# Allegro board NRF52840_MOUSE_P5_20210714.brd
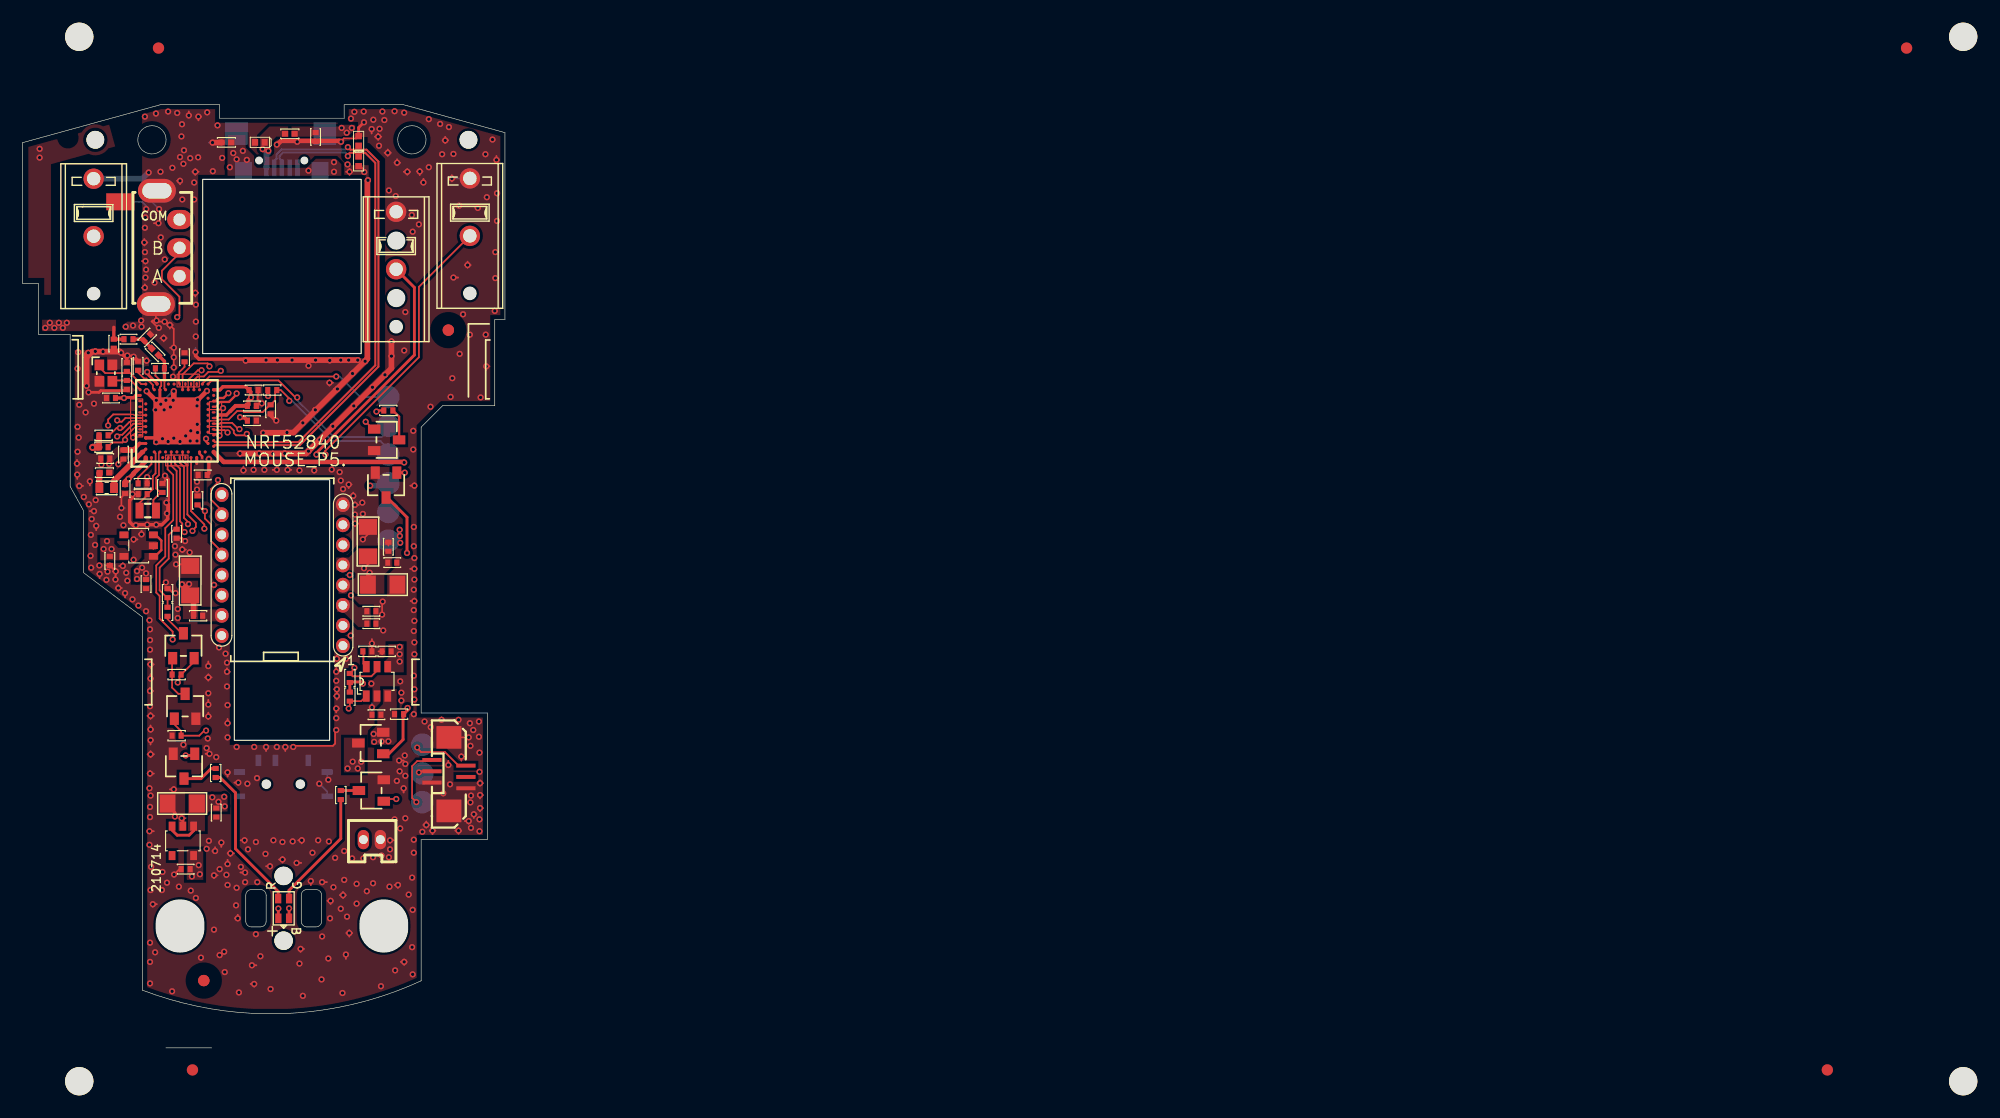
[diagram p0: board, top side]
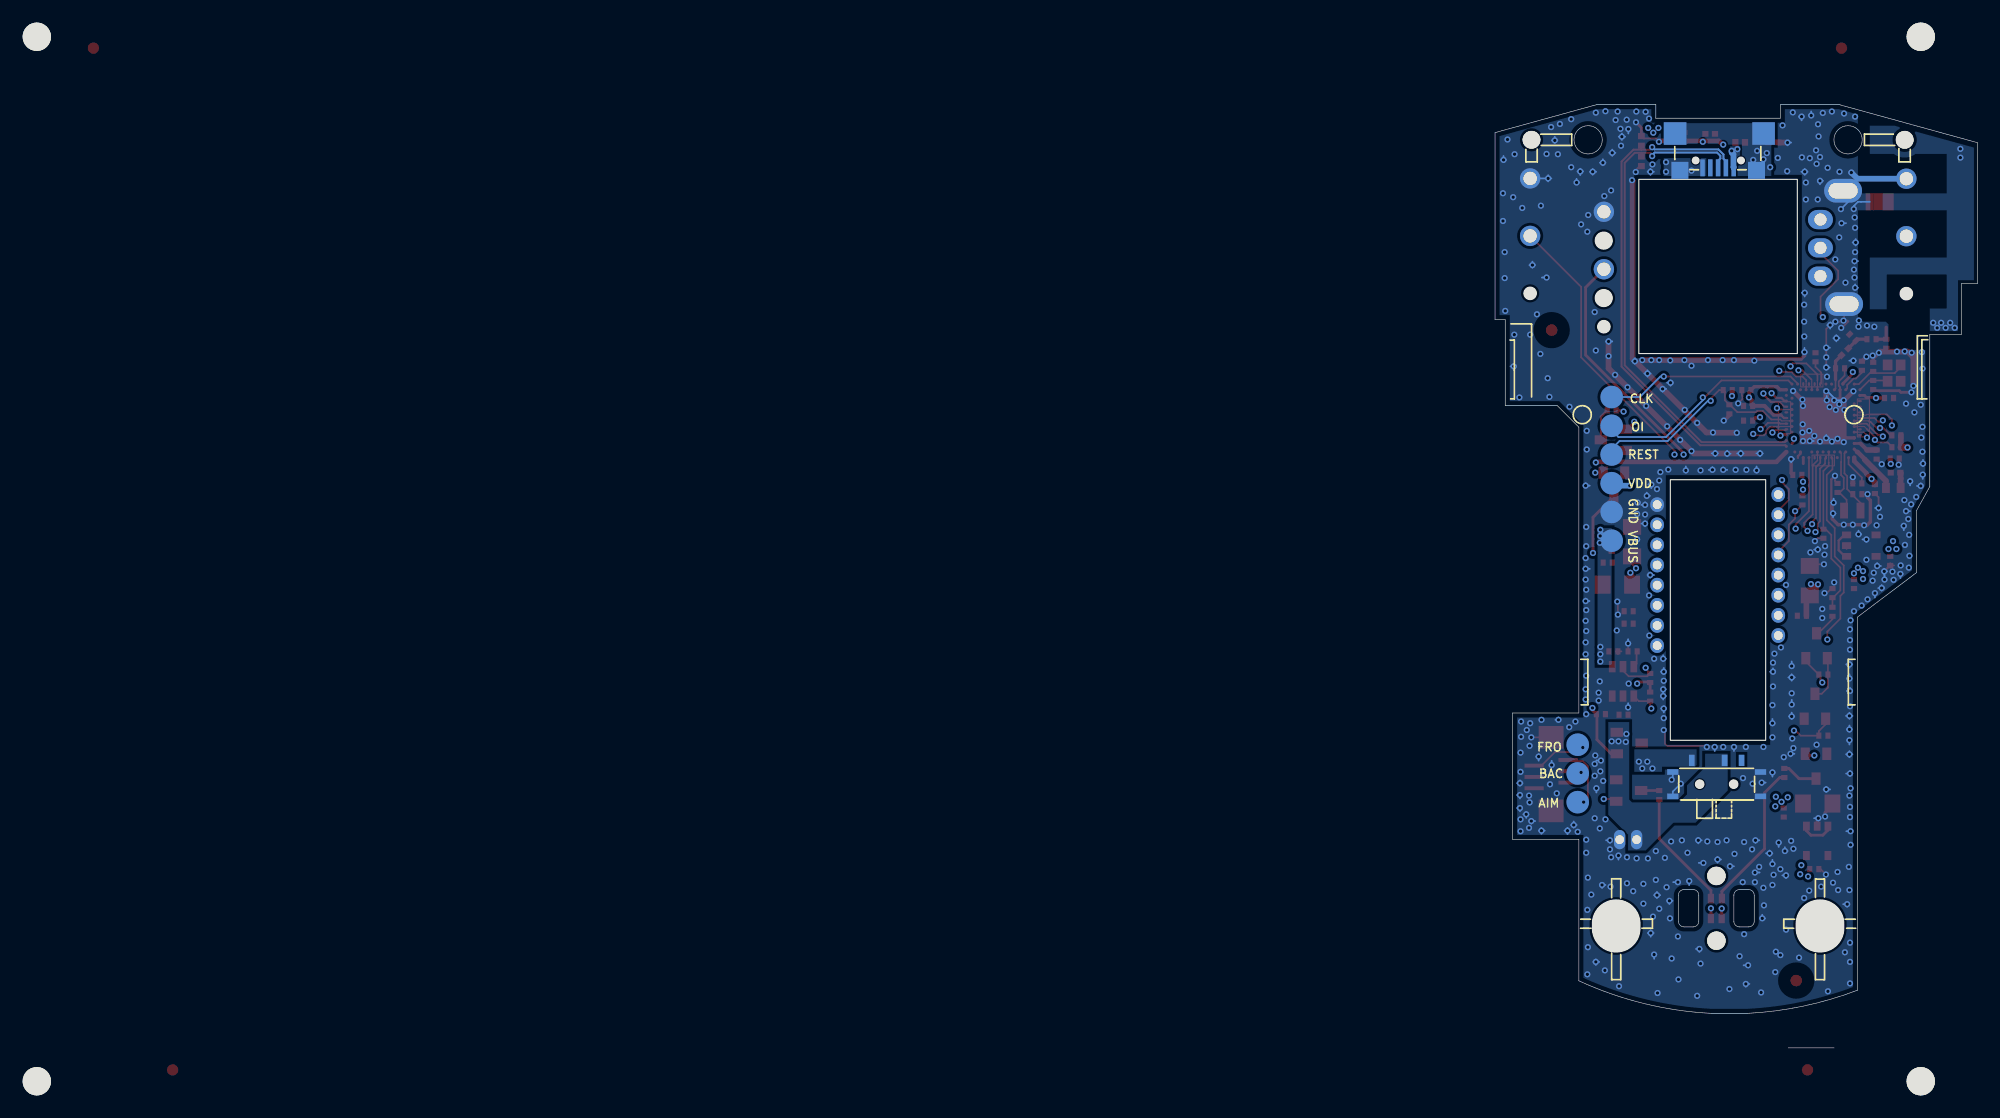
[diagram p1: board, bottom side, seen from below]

Outline 42.6 x 83.38 mm; copper layers: TOP, LAYER2, LAYER3, BOTTOM. Coordinates in mm from the lower left corner of the outline.
Outline path: circle c11.42,80.27 r1.25 ; rectangle 15.9,61.38 29.9,76.78 ; rectangle 18.7,27.19 27.12,50.23 ; circle c34.38,80.27 r1.25 ; 12.65,0 16.7,0 ; 0,80.03 0,67.56 1.41,67.56 1.41,63.06 4.2,63.06 4.2,49.62 5.38,47.48 5.38,42.01 10.6,38.07 10.6,5.09 arc(15.38,3.69) 20.32,3.05 23.48,3.05 arc(29.48,3.93) 35.2,5.93 35.2,18.42 41.05,18.42 41.05,29.6 35.2,29.6 35.2,54.87 37.1,56.77 41.7,56.77 41.7,64.37 42.6,64.37 42.6,80.91 33.61,83.38 28.4,83.38 28.4,82.18 17.4,82.18 17.4,83.38 12.19,83.38 0,80.03 ; 19.71,13.49 arc(19.85,13.85) 20.21,13.99 21.01,13.99 arc(21.36,13.85) 21.51,13.49 21.51,11.19 arc(21.36,10.84) 21.01,10.69 20.21,10.69 arc(19.85,10.84) 19.71,11.19 19.71,13.49 ; 24.61,13.49 arc(24.75,13.85) 25.11,13.99 25.91,13.99 arc(26.26,13.85) 26.41,13.49 26.41,11.19 arc(26.26,10.84) 25.91,10.69 25.11,10.69 arc(24.75,10.84) 24.61,11.19 24.61,13.49

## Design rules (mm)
net group RF2-MOUSE: nets N00074 N454705
net group USB: nets D_N D_P
net group 0_0762: nets BAT_ADC BLE_MODE BTN_RIGHT LED_B LED_G LED_R LLPM_MODE MOTION RESET SCLK WHELL_A WHELL_B WHELL_COM
net group W0_1R: nets N00048

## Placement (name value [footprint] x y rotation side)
C1  12pF  [C0402]  9.2 60.2 90 top
C2  12pF  [C0402]  9.2 58.6 270 top
C5  100nF  [C0402]  10.6 49.9 0 top
C6  4.7uF  [C0402]  15.9 50.65 0 top
C7  100nF  [C0402]  20.25 56.75 0 top
C8  100nF  [C0402]  20.4 58.15 0 top
C9  820pF  [C0402]  14.3 61.05 90 top
C11  100pF  [C0402]  10.2 60.3 90 top
C12  100nF  [C0402]  7.8 57.45 180 top
C14  1uF  [C0402]  9.05 49.4 270 top
C15  1uF  [C0402]  8.9 52.45 90 top
C16  47nF  [C0402]  7.3 52.1 180 top
C17  9pF  [C0402]  10.6 48.95 180 top
C18  9pF  [C0402]  12.35 49.5 90 top
C20  4.7uF  [C0402]  20.25 55.45 0 top
C22  100nF  [C0402]  25.87 80.52 90 top
C25  NC/0.8pF  [C0402]  12.12 60.08 180 top
C26  NC/0.5pF  [C0402]  11 62.8 45 top
C27  100nF  [C0402]  21.9 56.45 90 top
C28  10uF  [C0402]  30.8 37.5 0 top
C29  100nF  [C0402]  30.8 38.6 0 top
C30  4.7uF  [C0402]  31.25 29.45 180 top
C32  1uF  [C0402]  7.7 43.05 270 top
C33  1uF  [C0402]  14.4 15.8 180 top
C34  NC  [C0402]  13.6 45.45 270 top
C35  1uF  [C0402]  10.9 41 270 top
C36  1uF  [C0402]  17.1 20.8 270 top
C58  0R  [C0402]  9.35 62.65 180 top
C59  NC  [C0402]  8.05 62.25 270 top
C60  10uF  [C1206]  30.5 44.75 90 top
C61  10uF  [C1206]  31.8 40.95 0 top
C62  33uF  [C1206]  14.8 41.3 90 top
C63  100nF  [C0402]  32.3 44.3 90 top
C64  100nF  [C0402]  32.65 42.9 0 top
C65  10uF  [C1206]  14.1 21.6 180 top
D1  AZ5325-01F.R7G  [DFN1006P2E]  20.95 80.05 180 top
D2  AZ5325-01F.R7G  [DFN1006P2E]  29.67 78.38 270 top
D3  AZ5325-01F.R7G  [DFN1006P2E]  29.68 80.17 90 top
FB1  120R  [L0402]  23.6 80.8 0 top
FB2  120R  [L0402]  18 80.05 180 top
J1  Micro_USB  [PCBCOMPONENT_1_-_DUPLICATE]  24.28 77.28 180 bottom
J3  Scroll whell  [ENCODE-DIP-5PIN_-_DUPLICATE]  12.36 70.72 90 top
J4  SW_KEY  [KEYE]  6.27 71.75 0 top
J5  FPC_CON  [FPC_6PINLGUH]  39.15 22.95 270 top
J6  SW_KEY  [KEYE]  39.5 71.78 0 top
J7  SW_KEY  [KEYD1]  32.99 68.83 0 top
J8  POWER_SWITCH  [KEY-20210303]  23.03 23.31 180 bottom
J9  BAT_CON  [CON5-0303]  30.85 18.41 0 top
L2  10uH  [L0603]  7.42 49.5 0 top
L3  15nH  [L0402]  7.23 50.85 180 top
L4  0R  [L0402]  11.7 61.52 135 top
LED1  LED_RGB  [LED-SMD-1615-RGB_2]  23.05 12.32 180 top
MARK  -  [unnamed#3]  176.4 1.05 0 top
MARK#2  -  [unnamed#4]  0 85.38 0 top
MARK#3  -  [unnamed#5]  0 1.05 0 top
MARK#4  -  [unnamed#6]  176.4 85.38 0 top
NOREF  -  [unnamed]  23.05 15.2 0 top
NOREF#2  -  [unnamed#2]  37.6 63.45 0 top
NOREF#3  -  [unnamed#2]  16 5.95 0 top
NOREF#4  -  [unnamed]  39.38 80.27 0 top
NOREF#5  -  [unnamed]  23.05 9.48 0 top
NOREF#6  -  [unnamed]  13.9 10.78 0 top
NOREF#7  -  [unnamed]  31.9 10.78 0 top
NOREF#8  -  [unnamed]  6.42 80.27 0 top
Q2604  SI2301  [SOT_23]  14.2 35.55 0 top
Q2605  SI2301  [SOT_23]  30.75 26.95 90 top
R2  10K  [R0402]  22.05 58.15 180 top
R21  1M  [R0402]  7.15 53.1 180 top
R22  1M  [R0402]  7.15 54.15 180 top
R23  12R  [R0402]  15.5 38.2 180 top
R24  2K  [R0402]  17.05 24.3 270 top
R25  2K  [R0402]  28.1 22.35 270 top
R26  2K  [R0402]  32.3 56.35 180 top
R27  2K  [R0402]  30.45 35.05 180 top
R30  10K  [R0402]  15.45 48.4 90 top
R31  1M5  [R0402]  12.8 38.55 270 top
R32  180K  [R0402]  12.8 40.2 270 top
R33  1M  [R0402]  13.6 33 0 top
R34  1M  [R0402]  13.6 27.6 0 top
R42  1M  [R0402]  32.15 35.05 0 top
R43  1M  [R0402]  33.25 29.5 180 top
R44  10K  [R0402]  28.9 32.7 270 top
R45  10K  [R0402]  28.9 31.05 90 top
SHORT  short  [SHORT-1P5X1P8-2PIN]  9.16 74.79 0 top
TP2  TP_0.7  [TP_20]  32.3 54.99 180 bottom
TP3  TP_0.7  [TP_20]  32.3 57.53 180 bottom
TP4  TP_0.7  [TP_20]  32.3 47.38 180 bottom
TP5  TP_0.7  [TP_20]  32.3 52.45 180 bottom
TP6  TP_0.7  [TP_20]  32.3 44.83 180 bottom
TP7  TP_0.7  [TP_20]  32.3 49.91 180 bottom
TP8  TP_0.7  [TP_20]  35.3 26.8 180 bottom
TP9  TP_0.7  [TP_20]  35.3 24.26 180 bottom
TP10  TP_0.7  [TP_20]  35.3 21.72 180 bottom
U1  nRF52840-QIAA  [AQFN50P700X700X85_HS-74N]  13.62 55.43 90 top
U2  PAW3370DM  [PMW3360DM]  28.28 35.56 180 top
U1401  LDO 1.8V  [SOT-23-5L]  10.25 44.4 90 top
U1403  2N7002K-7  [SOT_23]  14.25 24.9 180 top
U1404  2N7002K-7  [SOT_23]  30.8 22.75 90 top
U1405  2N7002K-7  [SOT_23]  32.15 53.75 270 top
U1406  HX4057A  [SOT23-6]  31.3 32.4 90 top
U1407  LDO 3.3V  [SOT-23-5L]  14.15 18.3 180 top
U1408  2N7002K-7  [SOT_23]  14.35 30.2 0 top
U1409  2N7002K-7  [SOT_23]  32.1 49.75 180 top
X1  32MHz  [BT-XTAL_2016]  7.35 59.65 270 top
X2  32.768kHz  [XTAL_2012]  11.05 47.5 0 top

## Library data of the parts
C1 C2 C5-C9 C11 C12 C14-C18 C20 C22 C25 C27 = CAP
C26 C28-C30 C32-C36 C58-C65 = ceramic_Cap
D1-D3 = ESD_BI_DFN1006P2E
FB1 FB2 = IND_F
J1 = UN1159C-N1211-7H_1
J3 = Header-2_0
J4 J6 J7 = Header-2_3
J5 = Header-2_7
J8 = Header-2_5
J9 = Header-2_6
L2 L3 = IND
L4 = Inductors
LED1 = LED_RGB_1
Q2604 Q2605 = P-MOSFET_SOT_23
R2 = RES_1
R21-R27 R30-R34 R42-R45 = ceramic_Res
SHORT = TP_0
TP2-TP10 = TP
U1 = nRF52840_QIAA
U2 = DCDC_SY8254RAC_0
U1401 U1407 = DC_DC_SOT_23_2
U1403-U1405 U1408 U1409 = N-MOSFET_SOT_23
U1406 = DC_DC_SOT_23_4
X1 = CRYSTAL_3225
X2 = XTAL_2-pin

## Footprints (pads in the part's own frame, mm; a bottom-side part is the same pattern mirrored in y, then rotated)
AQFN50P700X700X85_HS-74N
  rect 4.15x4.15 smd: 74(0,0)
  oval 0.2x0.343 smd: A8(-1.25,3.25) A10(-0.75,3.25) A12(-0.25,3.25) A14(0.25,3.25) A16(0.75,3.25) A18(1.25,3.25) A20(1.75,3.25) AD10(-0.75,-3.25) AD12(-0.25,-3.25) AD14(0.25,-3.25) AD16(0.75,-3.25) AD18(1.25,-3.25)
  round 0.275 smd: A22(2.25,3.25) A23(2.75,3.25) AA24(3.25,-2.25) AB2(-2.75,-2.5) AC5(-2,-2.75) AC9(-1,-2.75) AC11(-0.5,-2.75) AC13(0,-2.75) AC15(0.5,-2.75) AC17(1,-2.75) AC19(1.5,-2.75) AC21(2,-2.75) AC24(3.25,-2.75) AD2(-2.75,-3.25) AD4(-2.25,-3.25) AD6(-1.75,-3.25) AD8(-1.25,-3.25) AD20(1.75,-3.25) AD22(2.25,-3.25) AD23(2.75,-3.25) B1(-3.25,2.75) B3(-2.5,2.75) B5(-2,2.75) B7(-1.5,2.75) B9(-1,2.75) B11(-0.5,2.75) B13(0,2.75) B15(0.5,2.75) B17(1,2.75) B19(1.5,2.75) B24(3.25,2.75) C1(-3.25,2.25) D2(-2.75,2) D23(2.75,2) E24(3.25,1.75) F2(-2.75,1.5) F23(2.75,1.5) G1(-3.25,1.25) H2(-2.75,1) H23(2.75,1) J24(3.25,0.75) K2(-2.75,0.5) L24(3.25,0.25) M2(-2.75,0) P2(-2.75,-0.5) P23(2.75,-0.5) T2(-2.75,-1) T23(2.75,-1) U1(-3.25,-1.25) V23(2.75,-1.5) W1(-3.25,-1.75) Y2(-2.75,-2) Y23(2.75,-2)
  oval 0.343x0.2 smd: J1(-3.25,0.75) L1(-3.25,0.25) N1(-3.25,-0.25) N24(3.25,-0.25) R1(-3.25,-0.75) R24(3.25,-0.75) U24(3.25,-1.25) W24(3.25,-1.75)
BT-XTAL_2016
  rect 0.95x0.85 smd: 1(-0.725,-0.575) 2(0.725,-0.575) 3(0.725,0.575) 4(-0.725,0.575)
C0402
  rect 0.45x0.55 smd: 1(-0.4,0) 2(0.4,0)
C1206
  rect 1.4x1.6 smd: 1(-1.3,0) 2(1.3,0)
CON5-0303
  oval 1x1.7 hole 0.7: 1(-0.75,0) 2(0.75,0)
DFN1006P2E
  rect 0.55x0.6 smd: 1(-0.425,0) 2(0.425,0)
ENCODE-DIP-5PIN_-_DUPLICATE
  oval 1.7x2.2 hole 1: 1(-2.5,-1.5) 2(0,-1.5) 3(2.5,-1.5)
  oval 2.1x3.35 hole 1.3x2.5: 4(-4.97,0.59) 5(5.05,0.5)
FPC_6PINLGUH
  rect 0.35x1.7 smd: 1(0,0) 2(-0.5,-3) 3(-1,0) 4(-1.5,-3) 5(-2,0) 6(-2.5,-3)
  rect 2x2.2 smd: 7(-4.5,-1.5) 8(2,-1.5)
KEY-20210303
  round 0.75 hole 0.75 unplated: (-1.5,0) (1.5,0)
  rect 0.5x1 smd: 1(-2.2,2.1) 2(0.7,2.1) 3(2.2,2.1)
  rect 1x0.5 smd: 4(3.875,1.075) 5(3.875,-1.075) 6(-3.875,-1.075) 7(-3.875,1.075)
KEYD1
  round 1.1 hole 1.1 unplated: (0,-5.08)
  round 1.5 hole 1.5 unplated: (0.011,2.532) (0.011,-2.548)
  round 1.8 hole 1.1: 1(0,0) 2(0,5.08)
KEYE
  round 1.1 hole 1.1 unplated: (0,-5.08)
  round 1.8 hole 1.1: 1(0,0) 2(0,5.08)
L0402
  rect 0.55x0.508 smd: 1(-0.424,0) 2(0.424,0)
L0603
  rect 0.7x0.9 smd: 1(-0.648,0) 2(0.648,0)
LED-SMD-1615-RGB_2
  rect 0.55x0.85 smd: 1(0.483,-0.876) 2(-0.483,-0.874) 3(-0.483,0.876) 4(0.467,0.876)
PCBCOMPONENT_1_-_DUPLICATE
  round 0.6 hole 0.6 unplated: (-0.605,1.17) (3.395,1.17)
  rect 0.4x1.5 smd: 1(2.75,0.521) 2(2.062,0.521) 3(1.375,0.521) 4(0.688,0.521) 5(0,0.521)
  rect 1.5x1.5 smd: 6(4.77,0.3) 9(-2,0.3)
  rect 2x2 smd: 7(5.391,3.55) 8(-2.421,3.55)
PMW3360DM
  oval 1.2x1.3 hole 0.7: 1(0,0) 2(0,-1.78) 3(0,-3.56) 4(0,-5.34) 5(0,-7.12) 6(0,-8.9) 7(0,-10.68) 8(0,-12.46) 9(10.7,-13.35) 10(10.7,-11.57) 11(10.7,-9.79) 12(10.7,-8.01) 13(10.7,-6.23) 14(10.7,-4.45) 15(10.7,-2.67) 16(10.7,-0.89)
R0402
  rect 0.45x0.55 smd: 1(-0.4,0) 2(0.4,0)
SHORT-1P5X1P8-2PIN
  rect 0.7x1.5 smd: 1(0.35,0)
  rect 1.8x1.5 smd: 2(-0.875,0)
SOT23-6
  rect 1x0.6 smd: 1(-1.3,0.95) 2(-1.3,0) 3(-1.3,-0.95) 4(1.3,-0.95) 5(1.3,0) 6(1.3,0.95)
SOT-23-5L
  rect 0.6x0.8 smd: 1(-0.95,-1.3) 2(0,-1.3) 3(0.95,-1.3) 4(0.95,1.3) 5(-0.95,1.3)
SOT_23
  rect 0.8x1.1 smd: 1(-0.95,-1.1) 2(0.95,-1.1) 3(0,1.1)
TP_20
  round 2 smd: 1(0,0)
unnamed
  round 1.6 hole 1.6 unplated: (0,0)
unnamed#2
  round 1 smd: (0,0) (0,0)
unnamed#3
  round 1 smd: (-17,-3)
  round 2.5 hole 2.5 unplated: (-5,-4)
unnamed#4
  round 2.5 hole 2.5 unplated: (5,4)
  round 1 smd: (12,3)
unnamed#5
  round 2.5 hole 2.5 unplated: (5,-4)
  round 1 smd: (15,-3)
unnamed#6
  round 1 smd: (-10,3)
  round 2.5 hole 2.5 unplated: (-5,4)
XTAL_2012
  rect 0.7x1.4 smd: 1(-0.725,0) 2(0.725,0)

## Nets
GND: C1.2 C2.2 C5.2 C6.2 C7.2 C8.2 C9.2 C11.2 C12.2 C14.2 C15.1 C16.2 C17.2 C18.2 C20.2 C22.1 C25.2 C26.2 C27.1 C28.2 C29.2 C30.2 C32.2 C33.2 C34.2 C35.2 C36.2 C59.2 C60.2 C61.2 C62.2 C63.2 C64.2 C65.2 D1.2 D2.2 D3.2 FB2.2 J3.4 J3.5 J4.2 J5.1 J5.2 J5.7 J5.8 J6.2 J7.2 J8.4 J8.5 J8.6 J8.7 J9.2 R27.1 R32.1 R34.1 R42.1 SHORT.1 TP4.1 U1.74 U1.B7(VSS) U1.F23(VSS_PA) U2.8(GND) U1401.2(GND) U1403.2(SOURCE) U1404.2(SOURCE) U1405.2(SOURCE) U1406.2(GND) U1407.2(GND) U1408.2(SOURCE) U1409.2(SOURCE) X1.2(GND1) X1.4(GND2)
VBAT_IN: C30.1 J8.2 J9.1 Q2604.2(SOURCE) Q2605.2(SOURCE) R33.2 R43.2 U1406.3(BAT)
VBAT_OUT: C36.1 C65.1 J8.1 Q2605.3(DRAIN) U1407.1(VIN) U1407.3(EN)
VBUS: D1.1 FB1.1 J1.1(VBUS)
VBUS_NRF: C22.2 FB1.2 R42.2 TP6.1 U1.AD2(VBUS) U1406.4(VCC) U1409.1(GATE)
VDD: C6.1 C7.1 C8.1 C12.1 C14.1 C32.1 C60.1 C61.1 C62.1 C63.1 C64.1 R2.2 R21.2 R22.2 R23.2 R30.2 R44.2 R45.2 TP7.1 U1.A22(VDD#A22) U1.AD14(VDD#AD14) U1.AD23(VDD#AD23) U1.B1(VDD#B1) U1.W1(VDD#W1) U1.Y2(VDDH) U2.4(VDD) U2.5(VDDIO) U1401.5(VOUT)
VDD_LED: C33.1 C35.1 LED1.4(A) U1401.1(VIN) U1401.3(EN) U1407.5(VOUT)
BAT_ADC: C34.1 R31.1 R32.2 U1.K2(P0.05/AIN3)
BAT_MON_EN: R34.2 U1.L1(P0.06) U1408.1(GATE)
BLE_MODE: U1.B17(P1.12)
BTN_LEFT: J4.1 U1.A12(P0.02/AIN0)
BTN_PCB_AIM: J5.6 TP10.1 U1.J1(P0.04/AIN2)
BTN_PCB_BACK: J5.4 TP9.1 U1.AD18(P0.22)
BTN_PCB_FRONT: J5.5 TP8.1 U1.AD20(P0.24)
BTN_RIGHT: J6.1 U1.B15(P1.14)
BTN_WHEEL: J7.1 U1.A14(P1.15)
D_N: D3.1 J1.2(D-) U1.AD4(D-)
D_P: D2.1 J1.3(D+) U1.AD6(D+)
DCCH: U1.AB2(DCCH)
DEC1: C5.1 U1.C1(DEC1)
DEC2: U1.A18(DEC2)
DEC3: C11.1 U1.D23(DEC3)
DEC4_6: C15.2 C16.1 L3.1 U1.B5(DEC4) U1.E24(DEC6)
LED_B: U1.V23(P1.03) U1405.1(GATE)
LED_G: U1.T23(P1.05) U1404.1(GATE)
LED_R: U1.P23(P1.07) U1403.1(GATE)
LLPM_MODE: U1.B19(P1.11)
MISO: R30.1 U1.AD10(P0.15) U2.12(MISO)
MOSI: U1.AD12(P0.17) U2.11(MOSI)
MOTION: U1.AC17(P0.21) U2.9(MOTION)
NCHRG: R45.1 U1.N1(P0.08) U1406.1(CHRG)
NSTDBY: R44.1 U1.P2(P1.08) U1406.5(STDBY)
PMW_RESET: U1.U1(P0.12) U2.7(RESET)
PWM_CS: U1.AD8(P0.13) U2.13(/CS)
RESET: C27.2 R2.1 TP5.1 U1.AC13(P0.18/RESET)
SCLK: U1.AC11(P0.16) U2.10(SCLK)
SW1: U1.R24(P1.06)
SWDCLK: TP3.1 U1.AA24(SWDCLK)
SWDIO: TP2.1 U1.AC24(SWDIO)
WHELL_A: J3.2 R22.1 U1.B13(P0.03/AIN1)
WHELL_B: J3.1 R21.1 U1.B11(P0.28/AIN4)
WHELL_COM: J3.3 U1.B9(P0.30/AIN6)
XC1: C1.1 U1.B24(XC1) X1.1(XIN)
XC2: C2.1 U1.A23(XC2) X1.3(XOUT)
N00013: C9.1 U1.N24(DEC5)
N00015: C20.1 U1.AC5(DECUSB)
N00024: L2.1 L3.2
N00025: L2.2 U1.B3(DCC)
N00047: C17.1 U1.D2(P0.00/XL1) X2.1(INP)
N00048: C18.1 U1.F2(P0.01/XL2) X2.2(OUT)
N00074: C25.1 L4.1 U1.H23(ANT)
N00235: FB2.1 J1.5(GND) J1.6(SHIELD2) J1.7(SHIELD3) J1.8(SHIELD4) J1.9(SHIELD5)
N372358: R23.1 U2.15(LED_P)
N372603: C28.1 C29.1 U2.3(VDDPIX)
N379055: LED1.1(C_RED) R24.2
N379073: LED1.2(C_GREEN) R25.2
N379080: LED1.3(C_BLUE) R26.2
N379134: R24.1 U1403.3(DRAIN)
N379451: R25.1 U1404.3(DRAIN)
N379621: R26.1 U1405.3(DRAIN)
N384910: R27.2 U1406.6(PROG)
N404039: Q2604.1(GATE) R33.1 U1408.3(DRAIN)
N404214: Q2604.3(DRAIN) R31.2
N445725: Q2605.1(GATE) R43.1 U1409.3(DRAIN)
N454705: C26.1 C58.1 L4.2
N455919: C58.2 C59.1 SHORT.2

Pads without a net: J1 4; J5 3; J8 3; U1 A8 A10 A16 A20 AC9 AC15 AC19 AC21 AD16 AD22 G1 H2 J24 L24 M2 R1 T2 U24 W24 Y23; U2 1 2 6 14 16; U1401 4; U1407 4

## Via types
v1: diameter 0.55, hole 0.3, TOP to BOTTOM, 613 vias

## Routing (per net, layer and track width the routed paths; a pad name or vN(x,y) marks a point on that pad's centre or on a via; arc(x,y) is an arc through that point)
GND: length 672.7
  TOP w0.15: 16.5,25.77 v1(16.5,26) ; v1(16.5,26) 16.5,26.15 ; v1(16.5,26) 16.16,26 ; v1(16.5,26) 16.65,26 ; v1(17,17.4) 17.18,17.4 ; v1(17,17.4) 17,17.73 ; v1(17,17.4) 16.76,17.4 ; v1(17,17.4) 17,17.22 ; 27.1,58.54 v1(27.1,58.8) ; v1(27.1,58.8) 27.41,58.8 ; v1(27.1,58.8) 26.9,58.8 ; v1(27.1,58.8) 27.1,59 ; C63.2 32.45,44.7 ; C63.2 32.3,44.4 ; C63.2 32.03,44.7 ; C63.2 32.3,44.85 ; U1409.2 31.15,51.1 ; U1409.2 31.15,50.6 ; U1409.2 31.4,50.85 ; U1409.2 30.83,50.85 ; v1(34.6,39.5) 34.6,39.73 ; v1(34.6,39.5) 34.6,39.35 ; v1(34.6,39.5) 34.26,39.5 ; v1(34.6,39.5) 34.75,39.5 ; v1(39.4,20.05) 39.4,20.22 ; v1(39.4,20.05) 39.06,20.05 ; v1(39.4,20.05) 39.4,19.82 ; v1(39.4,20.05) 39.57,20.05 ; 16.4,33.6 v1(16.4,33.75) ; v1(16.4,33.75) 16.56,33.75 ; v1(16.4,33.75) 16.4,34.16 ; v1(16.4,33.75) 16.25,33.75 ; 27.52,31.1 v1(27.75,31.1) ; v1(27.75,31.1) 27.75,30.8 ; v1(27.75,31.1) 27.95,31.1 ; v1(27.75,31.1) 27.75,31.3 ; J3.5 11.86,76 ; J3.5 11.63,75.77 ; J3.5 12.13,75.77 ; J3.5 11.86,75.48 ; v1(27.75,31.7) 27.75,31.87 ; v1(27.75,31.7) 27.75,31.37 ; v1(27.75,31.7) 27.52,31.7 ; v1(27.75,31.7) 27.92,31.7 ; J5.7 37.65,27.63 ; J5.7 37.65,27.12 ; J5.7 37.41,27.45 ; J5.7 v1(39.4,27.45) ; v1(35.65,19.7) 35.65,20.01 ; v1(35.65,19.7) 35.65,19.47 ; v1(35.65,19.7) 35.88,19.7 ; v1(35.65,19.7) 35.39,19.7 ; R42.1 31.92,35.05 ; R42.1 31.43,35.05 ; R42.1 31.75,35.22 ; R42.1 31.75,34.8 ; v1(19.2,52.55) 19.2,52.69 ; v1(19.2,52.55) 19.2,52.3 ; v1(19.2,52.55) 18.95,52.55 ; 39.3,68.97 v1(39.3,69.2) ; v1(39.3,69.2) 39.56,69.2 ; v1(39.3,69.2) 39.07,69.2 ; v1(39.3,69.2) 39.3,69.5 ; 16.4,32.47 v1(16.4,32.75) ; v1(16.4,32.75) 16.12,32.75 ; v1(16.4,32.75) 16.69,32.75 ; v1(16.4,32.75) 16.4,33.03 ; 11.55,44.11 U1401.2 ; U1401.2 11.55,44.58 ; U1401.2 11.37,44.4 ; U1401.2 11.82,44.4 ; v1(25.75,51.05) 25.94,51.05 ; v1(25.75,51.05) 25.75,50.86 ; v1(25.75,51.05) 25.54,51.05 ; v1(25.75,51.05) 25.75,51.35 ; C16.2 6.9,51.6 v1(6.95,51.55) ; v1(39.85,20.65) 39.85,20.84 ; v1(39.85,20.65) 39.66,20.65 ; v1(39.85,20.65) 40.1,20.65 ; v1(39.85,20.65) 39.85,20.33 ; 24.37,8.75 v1(24.55,8.75) ; v1(24.55,8.75) 24.55,8.93 ; v1(24.55,8.75) 24.85,8.75 ; v1(24.55,8.75) 24.55,8.48 ; v1(29.35,46.35) 29.67,46.35 ; v1(29.35,46.35) 29.35,46.54 ; v1(29.35,46.35) 29.16,46.35 ; v1(29.35,46.35) 29.35,46.11 ; v1(34.6,49.7) 34.77,49.7 ; v1(34.6,49.7) 34.6,49.53 ; v1(34.6,49.7) 34.6,49.91 ; v1(34.6,49.7) 34.24,49.7 ; 11.1,31.55 v1(11.25,31.55) ; v1(11.25,31.55) 11.53,31.55 ; v1(11.25,31.55) 11.25,31.84 ; v1(11.25,31.55) 11.25,31.4 ; v1(14.05,20.3) 14.35,20.3 ; v1(14.05,20.3) 14.05,20.49 ; v1(14.05,20.3) 13.86,20.3 ; v1(14.05,20.3) 14.05,20.11 ; v1(35.07,77.47) 35.32,77.47 ; v1(35.07,77.47) 35.07,77.16 ; v1(35.07,77.47) 34.83,77.47 ; v1(35.07,77.47) 35.07,77.72 ; v1(27.7,33.25) 27.7,33.58 ; v1(27.7,33.25) 27.94,33.25 ; v1(27.7,33.25) 27.52,33.25 ; v1(27.7,33.25) 27.7,33.05 ; 6.61,41.9 v1(6.8,41.9) ; v1(6.8,41.9) 6.8,42.07 ; v1(6.8,41.9) 6.97,41.9 ; v1(6.8,41.9) 6.8,41.53 ; v1(32.45,18.35) 32.78,18.35 ; v1(32.45,18.35) 32.27,18.35 ; v1(32.45,18.35) 32.45,18.53 ; v1(32.45,18.35) 32.45,18.12 ; v1(31.4,80.55) 31.68,80.55 ; v1(31.4,80.55) 31.4,80.27 ; v1(31.4,80.55) 31.4,80.83 ; v1(31.4,80.55) 31.11,80.55 ; v1(22.95,16.65) 22.95,16.87 ; v1(22.95,16.65) 23.17,16.65 ; v1(22.95,16.65) 22.65,16.65 ; v1(22.95,16.65) 22.95,16.38 ; 27.52,34.4 v1(27.75,34.4) ; v1(27.75,34.4) 27.75,34.7 ; v1(27.75,34.4) 27.75,34.19 ; v1(27.75,34.4) 27.96,34.4 ; v1(40.4,22.35) 40.65,22.35 ; v1(40.4,22.35) 40.23,22.35 ; v1(40.4,22.35) 40.4,22.05 ; v1(40.4,22.35) 40.4,22.52 ; v1(28.3,13.5) 28.3,13.78 ; v1(28.3,13.5) 28.55,13.5 ; v1(28.3,13.5) 28.3,13.25 ; v1(28.3,13.5) 28.02,13.5 ; 37.45,25 v1(37.6,25) ; v1(37.6,25) 37.79,25 ; v1(37.6,25) 37.6,24.85 ; v1(37.6,25) 37.6,25.38 ; v1(14.67,82.42) 14.67,82.78 ; v1(14.67,82.42) 14.89,82.42 ; v1(14.67,82.42) 14.53,82.42 ; v1(14.67,82.42) 14.67,82.28 ; 28,48.02 U2.8 ; U2.8 28.28,47.74 ; U2.8 28.57,48.02 ; U2.8 28.28,48.3 ; C8.2 20.8,57.67 20.75,57.62 20.75,57.35 21.11,56.99 ; v1(18.1,28.7) 18.3,28.7 ; v1(18.1,28.7) 18.1,28.51 ; v1(18.1,28.7) 18.1,29.07 ; v1(18.1,28.7) 17.91,28.7 ; v1(16.45,52.05) 16.45,52.22 ; v1(16.45,52.05) 16.62,52.05 ; v1(16.45,52.05) 16.25,52.05 ; J6.2 39.5,77.06 ; J6.2 39.87,76.86 ; J6.2 39.5,76.69 ; J6.2 39.33,76.86 ; v1(11.5,12.7) 11.85,12.7 ; v1(11.5,12.7) 11.5,12.85 ; v1(11.5,12.7) 11.35,12.7 ; v1(11.5,12.7) 11.5,12.48 ; v1(18.35,17.2) 18.35,17.44 ; v1(18.35,17.2) 18.66,17.2 ; v1(18.35,17.2) 18.11,17.2 ; v1(18.35,17.2) 18.35,16.94 ; 35.4,76.35 v1(35.4,76.5) ; v1(35.4,76.5) 35.4,76.83 ; v1(35.4,76.5) 35.55,76.5 ; v1(35.4,76.5) 35.16,76.5 ; v1(12.46,62.74) 12.71,62.74 ; v1(12.46,62.74) 12.18,62.74 ; v1(12.46,62.74) 12.46,63 ; v1(12.46,62.74) 12.46,62.46 ; 20.9,52.69 v1(20.9,52.55) 20.9,52.29 ; 22.09,51.1 v1(22.45,51.1) ; v1(22.45,51.1) 22.59,51.1 ; v1(22.45,51.1) 22.45,51.31 ; v1(22.45,51.1) 22.45,50.96 ; v1(10.5,45.4) 10.67,45.4 ; v1(10.5,45.4) 10.26,45.4 ; v1(10.5,45.4) 10.5,45.23 ; v1(10.5,45.4) 10.5,45.72 ; X1.4 7.93,60.74 ; X1.4 7.93,60.19 ; X1.4 8.11,60.37 ; X1.4 7.73,60.37 ; 38.5,18.92 v1(38.5,19.2) ; v1(38.5,19.2) 38.72,19.2 ; v1(38.5,19.2) 38.5,19.42 ; v1(38.5,19.2) 38.21,19.2 ; C32.2 7.92,42.65 ; C32.2 7.36,42.65 ; C32.2 7.7,42.43 ; C32.2 7.7,42.85 ; 10.55,67.2 v1(10.8,67.2) ; v1(10.8,67.2) 10.8,67.49 ; v1(10.8,67.2) 10.98,67.2 ; v1(10.8,67.2) 10.8,67.02 ; 33.25,25.24 v1(33.25,25.4) ; v1(33.25,25.4) 33.65,25.4 ; v1(33.25,25.4) 33.25,25.55 ; v1(33.25,25.4) 33.1,25.4 ; v1(40.95,60.25) 41.23,60.25 ; v1(40.95,60.25) 40.8,60.25 ; v1(40.95,60.25) 40.95,59.96 ; v1(40.95,60.25) 40.95,60.4 ; v1(9.05,40.2) 9.24,40.2 ; v1(9.05,40.2) 9.05,39.82 ; v1(9.05,40.2) 9.05,40.38 ; v1(9.05,40.2) 8.87,40.2 ; 28.92,48.8 v1(29.2,48.8) ; v1(29.2,48.8) 29.2,48.65 ; v1(29.2,48.8) 29.2,49.09 ; v1(29.2,48.8) 29.35,48.8 ; 21.51,16.05 v1(21.85,16.05) ; v1(21.85,16.05) 21.85,15.85 ; v1(21.85,16.05) 22.05,16.05 ; v1(21.85,16.05) 21.85,16.27 ; v1(40.4,21.2) 40.65,21.2 ; v1(40.4,21.2) 40.4,21.39 ; v1(40.4,21.2) 40.4,20.92 ; v1(40.4,21.2) 40.21,21.2 ; 11.04,29.35 v1(11.3,29.35) ; v1(11.3,29.35) 11.3,29.09 ; v1(11.3,29.35) 11.3,29.62 ; v1(11.3,29.35) 11.59,29.35 ; v1(11,50.45) C5.2 ; C5.2 11,49.75 ; C5.2 11.17,49.9 ; C5.2 10.85,49.9 ; v1(5,49.67) 5.33,49.67 ; v1(5,49.67) 5,49.91 ; v1(5,49.67) 4.85,49.67 ; v1(5,49.67) 5,49.53 ; 26.31,14.65 v1(26.45,14.65) ; v1(26.45,14.65) 26.87,14.65 ; v1(26.45,14.65) 26.45,14.79 ; v1(26.45,14.65) 26.45,14.5 ; 33.7,7.33 v1(33.7,7.6) ; v1(33.7,7.6) 33.92,7.6 ; v1(33.7,7.6) 33.7,7.82 ; v1(33.7,7.6) 33.4,7.6 ; v1(16.4,30.35) 16.4,30.76 ; v1(16.4,30.35) 16.4,30.21 ; v1(16.4,30.35) 16.55,30.35 ; v1(16.4,30.35) 16.26,30.35 ; 10.75,60.75 v1(10.95,60.75) ; v1(10.95,60.75) 10.95,60.55 ; v1(10.95,60.75) 11.15,60.75 ; v1(10.95,60.75) 10.95,60.95 ; v1(23.4,51.1) 23.4,51.34 ; v1(23.4,51.1) 23.4,50.93 ; v1(23.4,51.1) 23.73,51.1 ; v1(23.4,51.1) 23.23,51.1 ; 33.97,77.19 v1(33.97,77.45) ; v1(33.97,77.45) 33.97,77.69 ; v1(33.97,77.45) 34.21,77.45 ; v1(33.97,77.45) 33.67,77.45 ; v1(32.57,62.45) 32.57,62.68 ; v1(32.57,62.45) 32.25,62.45 ; v1(32.57,62.45) 32.81,62.45 ; D2.2 29.82,77.95 30.17,77.6 v1(30.17,77.42) ; v1(25.45,14.75) 25.64,14.75 ; v1(25.45,14.75) 25.45,14.39 ; v1(25.45,14.75) 25.28,14.75 ; v1(25.45,14.75) 25.45,14.92 ; 15.05,66.75 v1(15.25,66.75) ; v1(15.25,66.75) 15.25,66.43 ; v1(15.25,66.75) 15.5,66.75 ; v1(15.25,66.75) 15.25,66.95 ; v1(11.3,32.65) 11.5,32.65 ; v1(11.3,32.65) 11.13,32.65 ; v1(11.3,32.65) 11.3,32.48 ; v1(11.3,32.65) 11.3,33.02 ; 41.65,78.5 v1(41.85,78.5) ; v1(41.85,78.5) 42.07,78.5 ; v1(41.85,78.5) 41.85,78.84 ; v1(41.85,78.5) 41.85,78.3 ; 16.4,29.08 v1(16.4,29.3) ; v1(16.4,29.3) 16.4,29.63 ; v1(16.4,29.3) 16.18,29.3 ; v1(16.4,29.3) 16.63,29.3 ; v1(8.22,42.12) 8.44,42.12 ; v1(8.22,42.12) 8.22,41.82 ; v1(8.22,42.12) 7.96,42.12 ; v1(8.22,42.12) 8.22,42.34 ; v1(4.8,51.65) 5.04,51.65 ; v1(4.8,51.65) 4.6,51.65 ; v1(4.8,51.65) 4.8,51.97 ; v1(4.8,51.65) 4.8,51.42 ; v1(13.55,42.75) 14.65,42.75 C62.2 ; 12,72.75 v1(12,72.9) ; v1(12,72.9) 11.61,72.9 ; v1(12,72.9) 12.15,72.9 ; v1(12,72.9) 12,73.07 ; 36.84,29 v1(37,29) ; v1(37,29) 37.26,29 ; v1(37,29) 37,29.2 ; v1(37,29) 37,28.84 ; v1(24.2,16.35) 24.6,16.35 ; v1(24.2,16.35) 24.2,16.19 ; v1(24.2,16.35) 24.05,16.35 ; v1(24.2,16.35) 24.2,16.5 ; C34.2 14.1,45.05 v1(14.35,44.8) ; v1(11.2,19.15) 11.57,19.15 ; v1(11.2,19.15) 11.2,19.34 ; v1(11.2,19.15) 11.2,19 ; v1(11.2,19.15) 11.05,19.15 ; 37.63,76.86 v1(37.91,76.86) ; v1(37.91,76.86) 37.91,77.14 ; v1(37.91,76.86) 38.17,76.86 ; v1(37.91,76.86) 37.91,76.6 ; v1(4.82,50.67) 4.82,50.83 ; v1(4.82,50.67) 4.63,50.67 ; v1(4.82,50.67) 4.82,50.3 ; v1(4.82,50.67) 4.98,50.67 ; v1(15.25,77.45) 15.25,77.7 ; v1(15.25,77.45) 15.25,77.18 ; v1(15.25,77.45) 15.54,77.45 ; v1(15.25,77.45) 15,77.45 ; 31.97,79.12 v1(32.25,79.12) ; v1(32.25,79.12) 32.52,79.12 ; v1(32.25,79.12) 32.25,78.86 ; v1(32.25,79.12) 32.25,79.41 ; 11.04,25.95 v1(11.3,25.95) ; v1(11.3,25.95) 11.3,25.69 ; v1(11.3,25.95) 11.59,25.95 ; v1(11.3,25.95) 11.3,26.23 ; 13.87,44.05 v1(14.1,44.05) ; v1(14.1,44.05) 14.1,44.3 ; v1(14.1,44.05) 14.1,43.82 ; v1(14.1,44.05) 14.41,44.05 ; 11.1,28.15 v1(11.3,28.15) ; v1(11.3,28.15) 11.3,28.49 ; v1(11.3,28.15) 11.3,27.95 ; v1(11.3,28.15) 11.52,28.15 ; 30.65,30.1 v1(30.85,30.1) ; v1(30.85,30.1) 30.85,30.35 ; v1(30.85,30.1) 31.01,30.1 ; v1(30.85,30.1) 30.85,29.94 ; v1(27.2,13) 27.2,13.19 ; v1(27.2,13) 26.92,13 ; v1(27.2,13) 27.2,12.71 ; v1(27.2,13) 27.39,13 ; 20.45,5.4 v1(20.45,5.65) ; v1(20.45,5.65) 20.59,5.65 ; v1(20.45,5.65) 20.45,5.79 ; v1(20.45,5.65) 20.14,5.65 ; 18.75,11.45 v1(19,11.45) ; v1(19,11.45) 19.15,11.45 ; v1(19,11.45) 19,11.77 ; v1(19,11.45) 19,11.3 ; 13.64,76.65 v1(13.9,76.65) ; v1(13.9,76.65) 13.9,76.83 ; v1(13.9,76.65) 14.08,76.65 ; v1(13.9,76.65) 13.9,76.35 ; 8.53,42.6 v1(8.85,42.6) ; v1(8.85,42.6) 9,42.6 ; v1(8.85,42.6) 8.85,42.85 ; v1(8.85,42.6) 8.85,42.45 ; v1(10.85,69.55) 10.85,69.7 ; v1(10.85,69.55) 10.85,69.34 ; v1(10.85,69.55) 10.55,69.55 ; v1(10.85,69.55) 11,69.55 ; 40.4,23.18 v1(40.4,23.4) ; v1(40.4,23.4) 40.18,23.4 ; v1(40.4,23.4) 40.4,23.65 ; v1(40.4,23.4) 40.65,23.4 ; 34.6,42.18 v1(34.6,42.35) ; v1(34.6,42.35) 34.6,42.55 ; v1(34.6,42.35) 34.77,42.35 ; v1(34.6,42.35) 34.24,42.35 ; 21.11,56.99 20.89,56.99 C7.2 ; 21.11,56.99 v1(21.12,56.97) ; v1(30.05,44.95) 30.7,45.6 30.7,46 ; 11.25,24.04 v1(11.25,24.25) ; v1(11.25,24.25) 11.58,24.25 ; v1(11.25,24.25) 11.04,24.25 ; v1(11.25,24.25) 11.25,24.48 ; 37.09,80.22 v1(37.32,80.22) ; v1(37.32,80.22) 37.32,79.99 ; v1(37.32,80.22) 37.32,80.54 ; v1(37.32,80.22) 37.58,80.22 ; v1(19.5,51.05) 19.72,51.05 ; v1(19.5,51.05) 19.5,51.35 ; v1(19.5,51.05) 19.5,50.87 ; v1(19.5,51.05) 19.32,51.05 ; 28.58,77.45 v1(28.87,77.45) ; v1(28.87,77.45) 28.87,77.18 ; v1(28.87,77.45) 29.12,77.45 ; v1(28.87,77.45) 28.87,77.7 ; C17.2 v1(9.7,48.95) ; v1(27.7,28.1) 27.6,28 27.6,26.9 27.4,26.7 24,26.7 v1(23.9,26.6) ; v1(38.05,68.1) 38.05,68.25 ; v1(38.05,68.1) 38.46,68.1 ; v1(38.05,68.1) 38.05,67.95 ; v1(38.05,68.1) 37.9,68.1 ; R27.1 v1(30.85,35.75) ; v1(30.85,35.75) 30.85,36.12 ; v1(30.85,35.75) 31,35.75 ; v1(30.85,35.75) 30.66,35.75 ; v1(28.85,10.15) 28.85,10.4 ; v1(28.85,10.15) 28.85,9.84 ; v1(28.85,10.15) 28.6,10.15 ; v1(28.85,10.15) 29.1,10.15 ; v1(13,63.9) 13.35,63.55 v1(13.35,61.9) ; v1(13,63.9) 13.25,63.9 ; v1(13,63.9) 12.7,64.2 v1(12.54,64.2) 11.92,64.2 v1(11.83,64.29) ; v1(13,63.9) 13,63.59 ; v1(13,63.9) 13,64.13 ; v1(13,63.9) 12.77,63.9 ; v1(9.8,44.95) 10.14,44.95 ; v1(9.8,44.95) 9.66,44.95 ; v1(9.8,44.95) 9.8,45.09 ; v1(9.8,44.95) 9.8,44.73 ; C61.2 33.37,40.95 ; C61.2 33.1,41.23 ; C61.2 32.81,40.95 ; C61.2 33.1,40.68 ; v1(8.45,40.65) 8.45,40.92 ; v1(8.45,40.65) 8.75,40.65 ; v1(8.45,40.65) 8.22,40.65 ; v1(8.45,40.65) 8.45,40.42 ; 6.3,47.25 v1(6.3,47.45) ; v1(6.3,47.45) 6.3,47.66 ; v1(6.3,47.45) 5.95,47.45 ; v1(6.3,47.45) 6.5,47.45 ; v1(15.52,82.33) 15.52,82.5 ; v1(15.52,82.33) 15.52,81.99 ; v1(15.52,82.33) 15.35,82.33 ; v1(15.52,82.33) 15.76,82.33 ; v1(28.55,8.25) 28.55,8.41 ; v1(28.55,8.25) 28.74,8.25 ; v1(28.55,8.25) 28.55,7.88 ; v1(28.55,8.25) 28.39,8.25 ; v1(8.45,51.6) C15.1 ; v1(13.35,61.9) v1(13.35,61.05) v1(13.35,60.15) ; v1(13.35,61.9) 13.56,61.9 ; v1(13.35,61.9) 13.03,61.9 ; v1(27.7,30) 27.92,30 ; v1(27.7,30) 27.7,29.66 ; v1(27.7,30) 27.52,30 ; v1(27.7,30) 27.7,30.18 ; 6.5,45.76 v1(6.5,46.15) ; v1(6.5,46.15) 6.68,46.15 ; v1(6.5,46.15) 6.5,46.32 ; v1(6.5,46.15) 6.33,46.15 ; v1(19.05,23.45) 19.2,23.45 ; v1(19.05,23.45) 18.7,23.45 ; v1(19.05,23.45) 19.05,23.23 ; v1(19.05,23.45) 19.05,23.6 ; v1(30.25,60.7) 30.5,60.7 ; v1(30.25,60.7) 30.25,60.48 ; v1(30.25,60.7) 30.25,60.98 ; v1(30.25,60.7) 30.03,60.7 ; 28.65,49.8 v1(28.8,49.8) ; v1(28.8,49.8) 29.05,49.8 ; v1(28.8,49.8) 28.8,49.49 ; v1(28.8,49.8) 28.8,49.95 ; v1(10.75,71.2) 10.75,71.5 ; v1(10.75,71.2) 10.75,70.93 ; v1(10.75,71.2) 10.55,71.2 ; v1(10.75,71.2) 11.02,71.2 ; C33.2 13.85,15.8 v1(13.37,15.32) ; C25.2 11.72,59.42 12.24,58.91 12.24,58.52 12.12,58.4 U1.F23 ; C14.2 8.72,48.67 v1(8.72,47.72) ; 19.65,15.35 v1(19.65,15.5) ; v1(19.65,15.5) 19.79,15.5 ; v1(19.65,15.5) 19.65,15.64 ; v1(19.65,15.5) 19.24,15.5 ; v1(18.1,24.35) 18.3,24.35 ; v1(18.1,24.35) 17.91,24.35 ; v1(18.1,24.35) 18.1,23.98 ; v1(18.1,24.35) 18.1,24.54 ; v1(11.83,64.29) 11.77,64.35 J3.4 ; v1(11.83,64.29) 11.47,64.29 11.4,64.22 11.96,63.65 v1(12.03,63.65) ; v1(18.1,16.25) 18.1,16.62 ; v1(18.1,16.25) 18.29,16.25 ; v1(18.1,16.25) 18.1,16.06 ; v1(18.1,16.25) 17.91,16.25 ; v1(11.3,33.9) 11.58,33.9 ; v1(11.3,33.9) 11.3,34.15 ; v1(11.3,33.9) 11.05,33.9 ; v1(11.3,33.9) 11.3,33.61 ; v1(36.2,19.2) 36.46,19.2 ; v1(36.2,19.2) 35.95,19.2 ; v1(36.2,19.2) 36.2,18.89 ; v1(36.2,19.2) 36.2,19.45 ; v1(29.35,48) 29.68,48 ; v1(29.35,48) 29.35,48.24 ; v1(29.35,48) 29.35,47.8 ; v1(29.35,48) 29.15,48 ; v1(19.6,18.35) 19.77,18.35 ; v1(19.6,18.35) 19.6,18.52 ; v1(19.6,18.35) 19.26,18.35 ; v1(19.6,18.35) 19.6,18.12 ; 20.25,7.12 v1(20.25,7.3) ; v1(20.25,7.3) 20.64,7.3 ; v1(20.25,7.3) 20.09,7.3 ; v1(20.25,7.3) 20.25,7.46 ; D3.2 29.48,80.4 28.37,80.4 28.12,80.16 v1(28.12,80.1) ; 5.94,49.72 v1(5.94,50.09) ; v1(5.94,50.09) 6.14,50.09 ; v1(5.94,50.09) 5.94,50.28 ; v1(5.94,50.09) 5.74,50.09 ; 23.2,26.25 v1(23.2,26.6) ; v1(23.2,26.6) 22.98,26.6 ; v1(23.2,26.6) 23.4,26.6 ; v1(23.2,26.6) 23.2,26.79 ; v1(31.75,38.3) 31.75,39.4 v1(31.8,39.45) ; 16.73,15.25 v1(16.9,15.25) ; v1(16.9,15.25) 16.9,15 ; v1(16.9,15.25) 16.9,15.42 ; v1(16.9,15.25) 17.22,15.25 ; 24.35,18.35 v1(24.65,18.35) ; v1(24.65,18.35) 24.65,18.08 ; v1(24.65,18.35) 24.65,18.56 ; v1(24.65,18.35) 24.86,18.35 ; v1(27.8,58.25) 27.8,58.41 ; v1(27.8,58.25) 27.8,58 ; v1(27.8,58.25) 27.96,58.25 ; v1(27.8,58.25) 27.48,58.25 ; v1(33.07,78.25) 33.34,78.25 ; v1(33.07,78.25) 33.07,78.55 ; v1(33.07,78.25) 33.07,78.02 ; v1(33.07,78.25) 32.85,78.25 ; v1(38.75,25.75) 38.96,25.75 ; v1(38.75,25.75) 38.54,25.75 ; v1(38.75,25.75) 38.75,25.96 ; v1(38.75,25.75) 38.75,25.39 ; 32.85,14.4 v1(33.15,14.4) ; v1(33.15,14.4) 33.15,14.59 ; v1(33.15,14.4) 33.15,14.14 ; v1(33.15,14.4) 33.34,14.4 ; 18.05,33.08 v1(18.05,33.25) ; v1(18.05,33.25) 18.05,33.54 ; v1(18.05,33.25) 18.3,33.25 ; v1(18.05,33.25) 17.88,33.25 ; v1(12.57,50.57) 12.57,50.12 C18.2 ; v1(30.82,81.22) 30.82,81.39 ; v1(30.82,81.22) 30.82,80.84 ; v1(30.82,81.22) 30.66,81.22 ; v1(30.82,81.22) 31,81.22 ; v1(31.7,17) 31.7,17.17 ; v1(31.7,17) 31.7,16.65 ; v1(31.7,17) 31.87,17 ; v1(31.7,17) 31.49,17 ; R32.1 12.9,40.6 13.3,40.2 v1(13.5,40.2) ; v1(8.2,41.4) 8.2,41.8 ; v1(8.2,41.4) 8.37,41.4 ; v1(8.2,41.4) 8.04,41.4 ; v1(8.2,41.4) 8.2,41.24 ; 17.55,17.77 v1(17.55,18.15) ; v1(17.55,18.15) 17.55,18.31 ; v1(17.55,18.15) 17.36,18.15 ; v1(17.55,18.15) 17.71,18.15 ; v1(22.1,52.52) 22.1,52.69 ; v1(22.1,52.52) 21.8,52.52 ; v1(22.1,52.52) 22.1,52.3 ; v1(22.1,52.52) 22.32,52.52 ; 11.3,26.82 v1(11.3,27.2) ; v1(11.3,27.2) 11.49,27.2 ; v1(11.3,27.2) 11.3,27.36 ; v1(11.3,27.2) 11.14,27.2 ; v1(13.35,22.85) 13.35,23.08 ; v1(13.35,22.85) 13.35,22.62 ; v1(13.35,22.85) 13.01,22.85 ; v1(13.35,22.85) 13.58,22.85 ; v1(21.5,26.6) 21.7,26.6 ; v1(21.5,26.6) 21.5,26.79 ; v1(21.5,26.6) 21.29,26.6 ; v1(21.5,26.6) 21.5,26.25 ; v1(33.65,22.95) 33.84,22.95 ; v1(33.65,22.95) 33.65,23.12 ; v1(33.65,22.95) 33.65,22.57 ; v1(33.65,22.95) 33.48,22.95 ; v1(9.8,61.1) 9.7,61.2 v1(9.25,61.2) 8.95,61.2
  TOP w0.2: C32.2 v1(8.22,42.12) ; v1(12.57,50.57) 12.9,50.25 12.9,48.4 v1(12.7,48.2)
  TOP w0.25: v1(14.05,20.3) 14.15,20.2 U1407.2 ; C2.2 9.1,58.1 6.9,58.1 6.75,57.95 v1(5.82,57.95) ; U1.F23 12.12,56.93 U1.74 ; v1(13.45,20.45) 13.45,20.8 12.8,21.45 C65.2 ; v1(30.15,81.83) 29.68,81.35 D3.2
  TOP w0.3: v1(8.7,61.45) 9.2,60.95 C1.2 ; 12.27,53.93 U1.B7 ; v1(12.75,47.25) 12.81,47.19 12.81,46.76 12.3,46.25 v1(11.8,46.25) v1(11,46.25) 10.05,46.25 v1(10,46.2) 9.75,46.2 9.45,46.5 9.45,48.4 9.7,48.65 v1(9.7,48.95) ; C6.2 16.45,50.8 v1(16.45,52.05) ; C27.1 21.9,55.9 22.35,55.45 v1(22.4,55.45) ; v1(15.27,61.51) 15.27,61.19 15.57,60.89 19.56,60.89 v1(19.7,60.75)
  TOP w0.35: v1(9.8,61.1) C11.2 ; v1(12.75,47.25) 12.85,47.35 12.85,48.05 v1(12.7,48.2) ; 13.21,59.4 v1(13.28,59.33)
  TOP w0.4: v1(11.8,57.25) 11.75,57.25 v1(10.95,58.05) ; v1(22.45,79.85) 22.5,79.9 22.55,79.9 22.83,80.18 24.17,80.18 v1(24.25,80.1) 24.33,80.18 25.82,80.18 ; 25.87,80.12 25.82,80.18 ; 25.82,80.18 27.97,80.18 28.05,80.1 v1(28.12,80.1) ; v1(16.28,58.08) 15.5,57.3 v1(15.45,57.3)
  TOP w0.5: 6.44,61.55 v1(7.1,61.55) 8.6,61.55 v1(8.7,61.45) ; 6.44,61.55 6.15,61.55 5.65,61.05 ; 6.44,61.55 v1(6.42,61.57) ; 27.15,60.8 v1(27.13,60.77) ; 27.15,60.8 v1(28.1,60.8) v1(28.8,60.8) v1(29.6,60.8) ; 27.15,60.8 v1(25.87,60.8) v1(23.8,60.8) v1(22.5,60.8) v1(21.5,60.8) 19.75,60.8 v1(19.7,60.75) ; v1(13.3,57.25) 13.35,57.3 v1(13.35,58.05) ; v1(5.65,58.52) 5.65,61.05 ; 5.65,61.05 5.65,61.3 v1(5.8,61.45) ; v1(12.35,53.85) 12.27,53.93 ; v1(16.77,80.03) 17.56,80.03 FB2.2 ; v1(19.2,52.55) v1(20.9,52.55) v1(23.15,52.55) 25.05,52.55 v1(25.25,52.75) v1(26.25,53.75) 27.4,54.9 v1(27.4,54.95) 27.45,54.95 v1(29.25,56.75) v1(30.9,58.4) v1(32,59.5) 32.57,60.08 v1(32.57,61.15) v1(32.57,62.45) ; v1(21.25,54.38) 23.32,54.38 v1(23.35,54.4) 23.92,54.4 25.85,56.32 v1(25.85,56.4) 25.92,56.4 v1(29.14,59.61) 30.45,60.93 30.45,76.65 v1(30.5,76.7)
  LAYER2 w0.15: v1(38.05,68.1) 38.23,68.1 ; v1(38.05,68.1) 38.05,68.28 ; v1(38.05,68.1) 38.05,67.73 ; v1(38.05,68.1) 37.86,68.1 ; v1(32.9,6.85) 33.17,6.85 ; v1(32.9,6.85) 32.9,7.14 ; v1(32.9,6.85) 32.73,6.85 ; v1(32.9,6.85) 32.9,6.68 ; 23.64,18.25 v1(23.85,18.25) ; v1(23.85,18.25) 23.85,18.46 ; v1(23.85,18.25) 24.16,18.25 ; v1(23.85,18.25) 23.85,17.99 ; 31.6,82.77 v1(31.77,82.77) ; v1(31.77,82.77) 32.04,82.77 ; v1(31.77,82.77) 31.77,82.47 ; v1(31.77,82.77) 31.77,82.95 ; 13.5,82.65 v1(13.65,82.65) ; v1(13.65,82.65) 13.65,82.5 ; v1(13.65,82.65) 13.94,82.65 ; v1(13.65,82.65) 13.65,82.93 ; v1(40.3,28.85) 40.47,28.85 ; v1(40.3,28.85) 40.3,29.2 ; v1(40.3,28.85) 40.14,28.85 ; v1(40.3,28.85) 40.3,28.69 ; v1(28.4,14.85) 28.69,14.85 ; v1(28.4,14.85) 28.4,14.57 ; v1(28.4,14.85) 28.16,14.85 ; v1(28.4,14.85) 28.4,15.09 ; v1(18.05,33.25) 18.05,33.41 ; v1(18.05,33.25) 18.05,33.02 ; v1(18.05,33.25) 17.71,33.25 ; v1(18.05,33.25) 18.21,33.25 ; v1(24.45,7.45) 24.45,7.74 ; v1(24.45,7.45) 24.45,7.21 ; v1(24.45,7.45) 24.21,7.45 ; v1(24.45,7.45) 24.72,7.45 ; v1(20.6,18.2) 20.77,18.2 ; v1(20.6,18.2) 20.6,18.41 ; v1(20.6,18.2) 20.25,18.2 ; v1(20.6,18.2) 20.6,18.03 ; v1(17.1,25.7) 17.1,25.85 ; v1(17.1,25.7) 17.27,25.7 ; v1(17.1,25.7) 16.95,25.7 ; v1(17.1,25.7) 17.1,25.31 ; 10.62,50.45 v1(11,50.45) ; v1(11,50.45) 11,50.3 ; v1(11,50.45) 11.15,50.45 ; v1(11,50.45) 11,50.64 ; v1(30,48.2) 30.4,48.2 ; v1(30,48.2) 29.84,48.2 ; v1(30,48.2) 30,48.36 ; v1(30,48.2) 30,48.04 ; v1(35.87,82.1) 36.02,82.1 ; v1(35.87,82.1) 35.54,82.1 ; v1(35.87,82.1) 35.87,81.96 ; v1(35.87,82.1) 35.87,82.33 ; 16.05,26.5 v1(16.25,26.5) ; v1(16.25,26.5) 16.25,26.7 ; v1(16.25,26.5) 16.47,26.5 ; v1(16.25,26.5) 16.25,26.16 ; 40.05,74.25 v1(40.2,74.25) ; v1(40.2,74.25) 40.56,74.25 ; v1(40.2,74.25) 40.2,74.05 ; v1(40.2,74.25) 40.2,74.4 ; 31.3,81.25 v1(31.52,81.25) ; v1(31.52,81.25) 31.77,81.25 ; v1(31.52,81.25) 31.52,81.57 ; v1(31.52,81.25) 31.52,81.03 ; 6.69,51.55 v1(6.95,51.55) ; v1(6.95,51.55) 6.95,51.86 ; v1(6.95,51.55) 7.13,51.55 ; v1(6.95,51.55) 6.95,51.34 ; 11.48,46.25 v1(11.8,46.25) ; v1(11.8,46.25) 11.8,46 ; v1(11.8,46.25) 11.99,46.25 ; v1(11.8,46.25) 11.8,46.45 ; v1(5,49.67) 5,49.85 ; v1(5,49.67) 4.72,49.67 ; v1(5,49.67) 5.18,49.67 ; v1(5,49.67) 5,49.39 ; v1(34.4,15.05) 34.59,15.05 ; v1(34.4,15.05) 34.14,15.05 ; v1(34.4,15.05) 34.4,14.86 ; v1(34.4,15.05) 34.4,15.36 ; v1(10.8,72.5) 10.8,72.72 ; v1(10.8,72.5) 10.8,72.34 ; v1(10.8,72.5) 11.14,72.5 ; v1(10.8,72.5) 10.63,72.5 ; v1(12.55,69.7) 12.55,69.95 ; v1(12.55,69.7) 12.55,69.45 ; v1(12.55,69.7) 12.87,69.7 ; v1(12.55,69.7) 12.3,69.7 ; 11,37.8 v1(11.2,37.8) ; v1(11.2,37.8) 11.2,37.99 ; v1(11.2,37.8) 11.39,37.8 ; v1(11.2,37.8) 11.2,37.48 ; v1(33.45,30.7) 33.45,30.88 ; v1(33.45,30.7) 33.77,30.7 ; v1(33.45,30.7) 33.45,30.45 ; v1(33.45,30.7) 33.27,30.7 ; v1(40.35,24.4) 40.54,24.4 ; v1(40.35,24.4) 40.07,24.4 ; v1(40.35,24.4) 40.35,24.68 ; v1(40.35,24.4) 40.35,24.21 ; v1(17.62,78.67) 17.62,78.98 ; v1(17.62,78.67) 17.47,78.67 ; v1(17.62,78.67) 17.88,78.67 ; v1(17.62,78.67) 17.62,78.52 ; 18.85,12.32 v1(18.85,12.6) ; v1(18.85,12.6) 18.56,12.6 ; v1(18.85,12.6) 18.85,12.81 ; v1(18.85,12.6) 19.06,12.6 ; v1(10,46.2) 10,46.47 ; v1(10,46.2) 10,45.98 ; v1(10,46.2) 10.3,46.2 ; v1(10,46.2) 9.78,46.2 ; v1(15.5,78.72) 15.67,78.72 ; v1(15.5,78.72) 15.16,78.72 ; v1(15.5,78.72) 15.5,78.95 ; v1(15.5,78.72) 15.5,78.55 ; v1(15.45,54.4) 15.45,54.67 ; v1(15.45,54.4) 15.45,54.18 ; v1(15.45,54.4) 15.67,54.4 ; v1(15.45,54.4) 15.16,54.4 ; v1(37.8,57.55) 37.8,57.78 ; v1(37.8,57.55) 38.03,57.55 ; v1(37.8,57.55) 37.8,57.3 ; v1(37.8,57.55) 37.49,57.55 ; v1(14.2,78.15) 14.2,78.39 ; v1(14.2,78.15) 14.04,78.15 ; v1(14.2,78.15) 14.2,77.99 ; v1(14.2,78.15) 14.53,78.15 ; 34.38,41.4 v1(34.6,41.4) ; v1(34.6,41.4) 34.6,41.18 ; v1(34.6,41.4) 34.6,41.65 ; v1(34.6,41.4) 34.8,41.4 ; v1(27.3,51.12) 27.3,51.31 ; v1(27.3,51.12) 27.48,51.12 ; v1(27.3,51.12) 27.1,51.12 ; v1(27.3,51.12) 27.3,50.76 ; v1(12.7,48.2) 12.86,48.2 ; v1(12.7,48.2) 12.7,48.37 ; v1(12.7,48.2) 12.7,48.04 ; v1(12.7,48.2) 12.31,48.2 ; 8.92,61.2 v1(9.25,61.2) ; v1(9.25,61.2) 9.46,61.2 ; v1(9.25,61.2) 9.25,60.99 ; v1(9.25,61.2) 9.25,61.44 ; v1(11.25,21.3) 11.42,21.3 ; v1(11.25,21.3) 11,21.3 ; v1(11.25,21.3) 11.25,21.54 ; v1(11.25,21.3) 11.25,21.13 ; v1(6.1,46.75) 6.1,47.05 ; v1(6.1,46.75) 6.32,46.75 ; v1(6.1,46.75) 6.1,46.53 ; v1(6.1,46.75) 5.84,46.75 ; 32.4,14 v1(32.4,14.25) ; v1(32.4,14.25) 32.4,14.53 ; v1(32.4,14.25) 32.65,14.25 ; v1(32.4,14.25) 32.12,14.25 ; 27.93,80.1 v1(28.12,80.1) ; v1(28.12,80.1) 28.12,79.9 ; v1(28.12,80.1) 28.12,80.43 ; v1(28.12,80.1) 28.36,80.1 ; 12.91,56.65 v1(13.05,56.65) ; v1(13.05,56.65) 13.4,56.65 ; v1(13.05,56.65) 13.05,56.87 ; v1(13.05,56.65) 13.05,56.51 ; 11.8,53.36 v1(11.8,53.55) ; v1(11.8,53.55) 11.8,53.8 ; v1(11.8,53.55) 11.48,53.55 ; v1(11.8,53.55) 11.99,53.55 ; 25.85,56.15 v1(25.85,56.4) ; v1(25.85,56.4) 25.85,56.66 ; v1(25.85,56.4) 25.6,56.4 ; v1(25.85,56.4) 26.16,56.4 ; 11.13,77.1 v1(11.13,77.38) ; v1(11.13,77.38) 11.41,77.38 ; v1(11.13,77.38) 10.93,77.38 ; v1(11.13,77.38) 11.13,77.58 ; 24.45,50.77 v1(24.45,51.05) ; v1(24.45,51.05) 24.73,51.05 ; v1(24.45,51.05) 24.45,51.3 ; v1(24.45,51.05) 24.2,51.05 ; v1(13.35,58.05) 13.66,58.05 ; v1(13.35,58.05) 13.35,58.3 ; v1(13.35,58.05) 13.35,57.91 ; v1(13.35,58.05) 13.21,58.05 ; v1(7.4,41.38) 7.74,41.38 ; v1(7.4,41.38) 7.4,41.6 ; v1(7.4,41.38) 7.4,41.23 ; v1(7.4,41.38) 7.25,41.38 ; v1(24.2,16.35) 24.2,16.51 ; v1(24.2,16.35) 24.01,16.35 ; v1(24.2,16.35) 24.36,16.35 ; v1(24.2,16.35) 24.2,15.98 ; v1(10.85,68.1) 11.08,68.1 ; v1(10.85,68.1) 10.7,68.1 ; v1(10.85,68.1) 10.85,67.76 ; v1(10.85,68.1) 10.85,68.25 ; v1(7.5,42.1) 7.66,42.1 ; v1(7.5,42.1) 7.5,42.26 ; v1(7.5,42.1) 7.33,42.1 ; v1(7.5,42.1) 7.5,41.7 ; 27.89,50.15 v1(28.1,50.15) ; v1(28.1,50.15) 28.1,50.42 ; v1(28.1,50.15) 28.1,49.94 ; v1(28.1,50.15) 28.39,50.15 ; 28.97,36.11 v1(28.97,36.45) ; v1(28.97,36.45) 28.83,36.45 ; v1(28.97,36.45) 29.15,36.45 ; v1(28.97,36.45) 28.97,36.59 ; v1(40.35,26.1) 40.35,26.38 ; v1(40.35,26.1) 40.06,26.1 ; v1(40.35,26.1) 40.35,25.91 ; v1(40.35,26.1) 40.54,26.1 ; v1(19.27,16) 19.27,16.14 ; v1(19.27,16) 19.62,16 ; v1(19.27,16) 19.27,15.78 ; v1(19.27,16) 19.13,16 ; v1(19.85,23.35) 19.85,23.51 ; v1(19.85,23.35) 19.69,23.35 ; v1(19.85,23.35) 19.85,23.12 ; v1(19.85,23.35) 20.19,23.35 ; v1(34.55,36.85) 34.8,36.85 ; v1(34.55,36.85) 34.41,36.85 ; v1(34.55,36.85) 34.55,37.08 ; v1(34.55,36.85) 34.55,36.71 ; v1(11.2,22.95) 11.2,23.29 ; v1(11.2,22.95) 11.37,22.95 ; v1(11.2,22.95) 11.2,22.78 ; v1(11.2,22.95) 11,22.95 ; v1(34.55,32.9) 34.8,32.9 ; v1(34.55,32.9) 34.55,33.12 ; v1(34.55,32.9) 34.55,32.75 ; v1(34.55,32.9) 34.4,32.9 ; v1(12.57,50.57) 12.76,50.57 ; v1(12.57,50.57) 12.41,50.57 ; v1(12.57,50.57) 12.57,50.74 ; v1(12.57,50.57) 12.57,50.2 ; 12.65,57.04 v1(12.65,57.25) ; v1(12.65,57.25) 12.31,57.25 ; v1(12.65,57.25) 12.65,57.47 ; v1(12.65,57.25) 12.86,57.25 ; v1(14.67,82.42) 14.67,82.6 ; v1(14.67,82.42) 14.29,82.42 ; v1(14.67,82.42) 14.67,82.25 ; v1(14.67,82.42) 14.85,82.42 ; v1(10.5,63.75) 10.5,63.94 ; v1(10.5,63.75) 10.33,63.75 ; v1(10.5,63.75) 10.5,63.58 ; v1(10.5,63.75) 10.88,63.75 ; 18.84,4.9 v1(19.1,4.9) ; v1(19.1,4.9) 19.1,5.2 ; v1(19.1,4.9) 19.34,4.9 ; v1(19.1,4.9) 19.1,4.66 ; 13.8,14.06 v1(13.8,14.25) ; v1(13.8,14.25) 13.45,14.25 ; v1(13.8,14.25) 13.8,14.46 ; v1(13.8,14.25) 13.99,14.25 ; v1(9.15,42) 9.15,42.22 ; v1(9.15,42) 8.93,42 ; v1(9.15,42) 9.46,42 ; v1(9.15,42) 9.15,41.74 ; 34.4,29.5 v1(34.55,29.5) ; v1(34.55,29.5) 34.55,29.35 ; v1(34.55,29.5) 34.8,29.5 ; v1(34.55,29.5) 34.55,29.72 ; 15.45,57.01 v1(15.45,57.3) ; v1(15.45,57.3) 15.65,57.3 ; v1(15.45,57.3) 15.45,57.5 ; v1(15.45,57.3) 15.18,57.3 ; 12.2,71.5 v1(12.2,71.65) ; v1(12.2,71.65) 12.56,71.65 ; v1(12.2,71.65) 12.05,71.65 ; v1(12.2,71.65) 12.2,71.86 ; 33.75,25.63 v1(33.75,25.85) ; v1(33.75,25.85) 33.75,26.09 ; v1(33.75,25.85) 34.07,25.85 ; v1(33.75,25.85) 33.53,25.85 ; v1(17.21,81.55) 17.36,81.55 ; v1(17.21,81.55) 16.86,81.55 ; v1(17.21,81.55) 17.21,81.4 ; v1(17.21,81.55) 17.21,81.76 ; 12.05,13.95 v1(12.3,13.95) ; v1(12.3,13.95) 12.56,13.95 ; v1(12.3,13.95) 12.3,13.7 ; v1(12.3,13.95) 12.3,14.26 ; 15.15,74.81 v1(15.15,75) ; v1(15.15,75) 14.92,75 ; v1(15.15,75) 15.34,75 ; v1(15.15,75) 15.15,75.34 ; 26.83,23.7 v1(27,23.7) ; v1(27,23.7) 27,23.87 ; v1(27,23.7) 27,23.33 ; v1(27,23.7) 27.19,23.7 ; 17.23,15.8 v1(17.4,15.8) ; v1(17.4,15.8) 17.4,15.4 ; v1(17.4,15.8) 17.4,15.95 ; v1(17.4,15.8) 17.55,15.8 ; v1(25.25,60.3) 25.53,60.3 ; v1(25.25,60.3) 25.25,60.15 ; v1(25.25,60.3) 25.25,60.59 ; v1(25.25,60.3) 25.1,60.3 ; 38.35,29 v1(38.5,29) ; v1(38.5,29) 38.86,29 ; v1(38.5,29) 38.5,29.15 ; v1(38.5,29) 38.5,28.8 ; 29.9,82.77 v1(30.12,82.77) ; v1(30.12,82.77) 30.12,82.43 ; v1(30.12,82.77) 30.34,82.77 ; v1(30.12,82.77) 30.12,82.98 ; v1(4.9,61.5) 5.23,61.5 ; v1(4.9,61.5) 4.9,61.7 ; v1(4.9,61.5) 4.9,61.26 ; v1(4.9,61.5) 4.67,61.5 ; v1(13.7,38) 13.7,38.29 ; v1(13.7,38) 13.7,37.76 ; v1(13.7,38) 13.46,38 ; v1(13.7,38) 13.98,38 ; 11.46,56.4 v1(11.75,56.4) ; v1(11.75,56.4) 11.75,56.14 ; v1(11.75,56.4) 11.75,56.68 ; v1(11.75,56.4) 12.01,56.4 ; 11.83,64.13 v1(11.83,64.29) ; v1(11.83,64.29) 11.99,64.29 ; v1(11.83,64.29) 11.83,64.52 ; v1(11.83,64.29) 11.49,64.29 ; 34.66,72.8 v1(35,72.8) ; v1(35,72.8) 35.2,72.8 ; v1(35,72.8) 35,73.03 ; v1(35,72.8) 35,72.6 ; J6.2 39.65,76.86 ; J6.2 39.26,76.86 ; J6.2 39.5,77.01 ; J6.2 39.5,76.53 ; v1(9.8,43.15) 10,43.15 ; v1(9.8,43.15) 9.8,42.87 ; v1(9.8,43.15) 9.51,43.15 ; v1(9.8,43.15) 9.8,43.35 ; v1(17.35,35.4) 17.6,35.4 ; v1(17.35,35.4) 17.35,35.24 ; v1(17.35,35.4) 17.35,35.59 ; v1(17.35,35.4) 17.19,35.4 ; v1(23.35,54.4) 23.59,54.4 ; v1(23.35,54.4) 23.35,54.69 ; v1(23.35,54.4) 23.35,54.16 ; v1(23.35,54.4) 23.08,54.4 ; 34.46,35.85 v1(34.6,35.85) ; v1(34.6,35.85) 34.8,35.85 ; v1(34.6,35.85) 34.6,35.52 ; v1(34.6,35.85) 34.6,35.99 ; 38.65,64.85 v1(38.9,64.85) ; v1(38.9,64.85) 39.13,64.85 ; v1(38.9,64.85) 38.9,65.17 ; v1(38.9,64.85) 38.9,64.62 ; 23.9,26.43 v1(23.9,26.6) ; v1(23.9,26.6) 23.73,26.6 ; v1(23.9,26.6) 23.9,26.79 ; v1(23.9,26.6) 24.07,26.6 ; 16.01,58.08 v1(16.28,58.08) ; v1(16.28,58.08) 16.28,58.37 ; v1(16.28,58.08) 16.52,58.08 ; v1(16.28,58.08) 16.28,57.83 ; v1(34.4,8.9) 34.64,8.9 ; v1(34.4,8.9) 34.4,9.14 ; v1(34.4,8.9) 34.09,8.9 ; v1(34.4,8.9) 34.4,8.64 ; 25.87,60.65 v1(25.87,60.8) ; v1(25.87,60.8) 25.87,60.98 ; v1(25.87,60.8) 26.03,60.8 ; v1(25.87,60.8) 25.73,60.8 ; 36.87,81.33 v1(36.87,81.67) ; v1(36.87,81.67) 36.72,81.67 ; v1(36.87,81.67) 37.1,81.67 ; v1(36.87,81.67) 36.87,81.83 ; v1(14.85,54.55) 15.01,54.55 ; v1(14.85,54.55) 14.85,54.71 ; v1(14.85,54.55) 14.85,54.15 ; v1(14.85,54.55) 14.69,54.55 ; v1(11.25,31.55) 11.42,31.55 ; v1(11.25,31.55) 11,31.55 ; v1(11.25,31.55) 11.25,31.72 ; v1(11.25,31.55) 11.25,31.31 ; 17.23,8.2 v1(17.4,8.2) ; v1(17.4,8.2) 17.4,8.05 ; v1(17.4,8.2) 17.55,8.2 ; v1(17.4,8.2) 17.4,8.6 ; v1(33.25,25.4) 33.41,25.4 ; v1(33.25,25.4) 33.25,25.56 ; v1(33.25,25.4) 33.25,25.03 ; v1(33.25,25.4) 33.06,25.4 ; v1(13.9,53.6) 13.9,53.76 ; v1(13.9,53.6) 13.74,53.6 ; v1(13.9,53.6) 13.9,53.4 ; v1(13.9,53.6) 14.26,53.6 ; 9.7,39.49 v1(9.7,39.65) ; v1(9.7,39.65) 9.7,39.94 ; v1(9.7,39.65) 9.54,39.65 ; v1(9.7,39.65) 9.97,39.65 ; v1(37.15,22.5) 37.15,22.71 ; v1(37.15,22.5) 37.15,22.23 ; v1(37.15,22.5) 36.94,22.5 ; v1(37.15,22.5) 37.44,22.5 ; v1(29,82.15) 29,82.42 ; v1(29,82.15) 29,81.87 ; v1(29,82.15) 29.27,82.15 ; v1(29,82.15) 28.8,82.15 ; v1(37.6,25) 37.75,25 ; v1(37.6,25) 37.6,24.85 ; v1(37.6,25) 37.2,25 ; v1(37.6,25) 37.6,25.17 ; 27.3,16.8 v1(27.6,16.8) ; v1(27.6,16.8) 27.6,16.55 ; v1(27.6,16.8) 27.6,17.07 ; v1(27.6,16.8) 27.85,16.8 ; v1(11.3,32.65) 11.45,32.65 ; v1(11.3,32.65) 11,32.65 ; v1(11.3,32.65) 11.3,32.49 ; v1(11.3,32.65) 11.3,32.8 ; 11.2,17.69 v1(11.2,17.95) ; v1(11.2,17.95) 11.44,17.95 ; v1(11.2,17.95) 11.2,18.2 ; v1(11.2,17.95) 11,17.95 ; v1(33.8,24.05) 33.97,24.05 ; v1(33.8,24.05) 33.63,24.05 ; v1(33.8,24.05) 33.8,24.44 ; v1(33.8,24.05) 33.8,23.88 ; 39.19,28.7 v1(39.5,28.7) ; v1(39.5,28.7) 39.5,28.45 ; v1(39.5,28.7) 39.73,28.7 ; v1(39.5,28.7) 39.5,28.93 ; v1(23.4,51.1) 23.55,51.1 ; v1(23.4,51.1) 23.12,51.1 ; v1(23.4,51.1) 23.4,51.25 ; v1(23.4,51.1) 23.4,50.82 ; 11.2,18.82 v1(11.2,19.15) ; v1(11.2,19.15) 11.2,19.33 ; v1(11.2,19.15) 11.38,19.15 ; v1(11.2,19.15) 11,19.15 ; 19.48,14.65 v1(19.65,14.65) ; v1(19.65,14.65) 19.84,14.65 ; v1(19.65,14.65) 19.65,14.82 ; v1(19.65,14.65) 19.65,14.27 ; 30.95,14.28 v1(30.95,14.55) ; v1(30.95,14.55) 30.69,14.55 ; v1(30.95,14.55) 31.25,14.55 ; v1(30.95,14.55) 30.95,14.81 ; v1(12.85,53.6) 13.13,53.6 ; v1(12.85,53.6) 12.61,53.6 ; v1(12.85,53.6) 12.85,53.84 ; v1(12.85,53.6) 12.85,53.31 ; v1(24.25,80.1) 24.4,80.1 ; v1(24.25,80.1) 24.25,80.38 ; v1(24.25,80.1) 24.25,79.95 ; v1(24.25,80.1) 23.97,80.1 ; 31.85,36.64 v1(31.85,36.9) ; v1(31.85,36.9) 31.55,36.9 ; v1(31.85,36.9) 31.85,37.14 ; v1(31.85,36.9) 32.09,36.9 ; v1(17.92,34.85) 18.18,34.85 ; v1(17.92,34.85) 17.92,35.16 ; v1(17.92,34.85) 17.92,34.66 ; v1(17.92,34.85) 17.74,34.85 ; 30.95,16.55 v1(30.95,16.85) ; v1(30.95,16.85) 30.73,16.85 ; v1(30.95,16.85) 31.21,16.85 ; v1(30.95,16.85) 30.95,17.07 ; v1(24.75,55.25) 24.75,55.56 ; v1(24.75,55.25) 25.01,55.25 ; v1(24.75,55.25) 24.49,55.25 ; v1(24.75,55.25) 24.75,54.99 ; 26.17,6.05 v1(26.4,6.05) ; v1(26.4,6.05) 26.4,6.3 ; v1(26.4,6.05) 26.4,5.82 ; v1(26.4,6.05) 26.72,6.05 ; v1(20.25,7.3) 20.4,7.3 ; v1(20.25,7.3) 20.05,7.3 ; v1(20.25,7.3) 20.25,6.94 ; v1(20.25,7.3) 20.25,7.45 ; 10.9,38.35 v1(10.9,38.6) ; v1(10.9,38.6) 10.62,38.6 ; v1(10.9,38.6) 10.9,38.86 ; v1(10.9,38.6) 11.16,38.6 ; 32.95,75.08 v1(32.95,75.3) ; v1(32.95,75.3) 33.18,75.3 ; v1(32.95,75.3) 32.95,75.64 ; v1(32.95,75.3) 32.73,75.3 ; v1(15.4,56.75) 15.64,56.75 ; v1(15.4,56.75) 15.4,56.42 ; v1(15.4,56.75) 15.19,56.75 ; v1(15.4,56.75) 15.4,56.96 ; v1(33.8,20.3) 33.98,20.3 ; v1(33.8,20.3) 33.8,20.49 ; v1(33.8,20.3) 33.61,20.3 ; v1(33.8,20.3) 33.8,19.92 ; 41.72,73.1 v1(41.9,73.1) ; v1(41.9,73.1) 42.2,73.1 ; v1(41.9,73.1) 41.9,73.28 ; v1(41.9,73.1) 41.9,72.91 ; 20.85,8.1 v1(21,8.1) ; v1(21,8.1) 21.29,8.1 ; v1(21,8.1) 21,7.83 ; v1(21,8.1) 21,8.25 ; 14.35,44.59 v1(14.35,44.8) ; v1(14.35,44.8) 14.35,45.03 ; v1(14.35,44.8) 14.01,44.8 ; v1(14.35,44.8) 14.56,44.8 ; 14.25,79.07 v1(14.25,79.35) ; v1(14.25,79.35) 14.25,79.57 ; v1(14.25,79.35) 14.53,79.35 ; v1(14.25,79.35) 14.03,79.35 ; 30.25,13.85 v1(30.4,13.85) ; v1(30.4,13.85) 30.4,13.7 ; v1(30.4,13.85) 30.56,13.85 ; v1(30.4,13.85) 30.4,14.26 ; v1(8.9,46.2) 9.17,46.2 ; v1(8.9,46.2) 8.9,46.5 ; v1(8.9,46.2) 8.9,45.95 ; v1(8.9,46.2) 8.65,46.2 ; 10.68,74.15 v1(10.91,74.15) ; v1(10.91,74.15) 11.1,74.15 ; v1(10.91,74.15) 10.91,73.97 ; v1(10.91,74.15) 10.91,74.48 ; v1(26.45,14.65) 26.62,14.65 ; v1(26.45,14.65) 26.45,14.82 ; v1(26.45,14.65) 26.27,14.65 ; v1(26.45,14.65) 26.45,14.27 ; 11.25,35.84 v1(11.25,36.05) ; v1(11.25,36.05) 11.25,36.25 ; v1(11.25,36.05) 11,36.05 ; v1(11.25,36.05) 11.45,36.05 ; v1(28.1,12.3) 28.41,12.3 ; v1(28.1,12.3) 28.1,12.52 ; v1(28.1,12.3) 27.88,12.3 ; v1(28.1,12.3) 28.1,12.04 ; v1(37,29) 37.16,29 ; v1(37,29) 36.66,29 ; v1(37,29) 37,28.78 ; v1(37,29) 37,29.16 ; 11.81,74.15 v1(12.05,74.15) ; v1(12.05,74.15) 12.23,74.15 ; v1(12.05,74.15) 12.05,73.97 ; v1(12.05,74.15) 12.05,74.48 ; v1(26.2,23.35) 26.2,23.56 ; v1(26.2,23.35) 26.2,23.07 ; v1(26.2,23.35) 25.92,23.35 ; v1(26.2,23.35) 26.41,23.35
  LAYER3 w0.15: 15.18,57.3 v1(15.45,57.3) ; v1(15.45,57.3) 15.45,57.01 ; v1(15.45,57.3) 15.65,57.3 ; v1(15.45,57.3) 15.45,57.5 ; v1(39.5,28.7) 39.5,28.93 ; v1(39.5,28.7) 39.19,28.7 ; v1(39.5,28.7) 39.73,28.7 ; v1(39.5,28.7) 39.5,28.45 ; v1(34.55,29.5) 34.55,29.72 ; v1(34.55,29.5) 34.4,29.5 ; v1(34.55,29.5) 34.55,29.35 ; v1(34.55,29.5) 34.8,29.5 ; 17.19,35.4 v1(17.35,35.4) ; v1(17.35,35.4) 17.6,35.4 ; v1(17.35,35.4) 17.35,35.24 ; v1(17.35,35.4) 17.35,35.59 ; 34.4,8.64 v1(34.4,8.9) ; v1(34.4,8.9) 34.64,8.9 ; v1(34.4,8.9) 34.09,8.9 ; v1(34.4,8.9) 34.4,9.14 ; 10.85,67.76 v1(10.85,68.1) ; v1(10.85,68.1) 10.7,68.1 ; v1(10.85,68.1) 11.08,68.1 ; v1(10.85,68.1) 10.85,68.25 ; 36.72,81.67 v1(36.87,81.67) ; v1(36.87,81.67) 36.87,81.33 ; v1(36.87,81.67) 36.87,81.83 ; v1(36.87,81.67) 37.1,81.67 ; v1(27.6,16.8) 27.6,17.07 ; v1(27.6,16.8) 27.85,16.8 ; v1(27.6,16.8) 27.6,16.55 ; v1(27.6,16.8) 27.3,16.8 ; 20.25,6.94 v1(20.25,7.3) ; v1(20.25,7.3) 20.4,7.3 ; v1(20.25,7.3) 20.05,7.3 ; v1(20.25,7.3) 20.25,7.45 ; v1(17.92,34.85) 18.18,34.85 ; v1(17.92,34.85) 17.92,34.66 ; v1(17.92,34.85) 17.92,35.16 ; v1(17.92,34.85) 17.74,34.85 ; v1(24.25,80.1) 24.4,80.1 ; v1(24.25,80.1) 24.25,79.95 ; v1(24.25,80.1) 23.97,80.1 ; v1(24.25,80.1) 24.25,80.38 ; 11,21.3 v1(11.25,21.3) ; v1(11.25,21.3) 11.42,21.3 ; v1(11.25,21.3) 11.25,21.54 ; v1(11.25,21.3) 11.25,21.13 ; 19.85,23.12 v1(19.85,23.35) ; v1(19.85,23.35) 19.69,23.35 ; v1(19.85,23.35) 19.85,23.51 ; v1(19.85,23.35) 20.19,23.35 ; v1(38.5,29) 38.5,29.15 ; v1(38.5,29) 38.5,28.8 ; v1(38.5,29) 38.35,29 ; v1(38.5,29) 38.86,29 ; 27.93,80.1 v1(28.12,80.1) ; v1(28.12,80.1) 28.36,80.1 ; v1(28.12,80.1) 28.12,80.32 ; v1(28.12,80.1) 28.12,79.9 ; 12.91,56.65 v1(13.05,56.65) ; v1(13.05,56.65) 13.34,56.65 ; v1(13.05,56.65) 13.05,56.87 ; v1(13.05,56.65) 13.05,56.51 ; 25.1,60.3 v1(25.25,60.3) ; v1(25.25,60.3) 25.25,60.59 ; v1(25.25,60.3) 25.53,60.3 ; v1(25.25,60.3) 25.25,60.15 ; 34.4,32.9 v1(34.55,32.9) ; v1(34.55,32.9) 34.55,33.12 ; v1(34.55,32.9) 34.8,32.9 ; v1(34.55,32.9) 34.55,32.75 ; 11.48,53.55 v1(11.8,53.55) ; v1(11.8,53.55) 11.8,53.36 ; v1(11.8,53.55) 11.99,53.55 ; v1(11.8,53.55) 11.8,53.8 ; 16.01,58.08 v1(16.28,58.08) ; v1(16.28,58.08) 16.52,58.08 ; v1(16.28,58.08) 16.28,57.83 ; v1(16.28,58.08) 16.28,58.37 ; v1(20.6,18.2) 20.6,18.41 ; v1(20.6,18.2) 20.77,18.2 ; v1(20.6,18.2) 20.25,18.2 ; v1(20.6,18.2) 20.6,18.03 ; v1(30.95,16.85) 31.21,16.85 ; v1(30.95,16.85) 30.73,16.85 ; v1(30.95,16.85) 30.95,16.55 ; v1(30.95,16.85) 30.95,17.07 ; v1(9.25,61.2) 9.46,61.2 ; v1(9.25,61.2) 9.25,60.99 ; v1(9.25,61.2) 8.92,61.2 ; v1(9.25,61.2) 9.25,61.44 ; 12.05,71.65 v1(12.2,71.65) ; v1(12.2,71.65) 12.2,71.5 ; v1(12.2,71.65) 12.56,71.65 ; v1(12.2,71.65) 12.2,71.86 ; 13.35,57.91 v1(13.35,58.05) ; v1(13.35,58.05) 13.52,58.05 ; v1(13.35,58.05) 13.21,58.05 ; v1(13.35,58.05) 13.35,58.3 ; v1(11.2,17.95) 11.2,18.2 ; v1(11.2,17.95) 11.44,17.95 ; v1(11.2,17.95) 11,17.95 ; v1(11.2,17.95) 11.2,17.69 ; v1(33.45,30.7) 33.62,30.7 ; v1(33.45,30.7) 33.45,30.45 ; v1(33.45,30.7) 33.27,30.7 ; v1(33.45,30.7) 33.45,30.88 ; 24.2,51.05 v1(24.45,51.05) ; v1(24.45,51.05) 24.45,51.3 ; v1(24.45,51.05) 24.73,51.05 ; v1(24.45,51.05) 24.45,50.77 ; v1(11.2,37.8) 11.2,37.99 ; v1(11.2,37.8) 11,37.8 ; v1(11.2,37.8) 11.2,37.48 ; v1(11.2,37.8) 11.39,37.8 ; 6.73,51.55 v1(6.95,51.55) ; v1(6.95,51.55) 7.13,51.55 ; v1(6.95,51.55) 6.95,51.86 ; v1(6.95,51.55) 6.95,51.34 ; v1(6.1,46.75) 6.1,47.05 ; v1(6.1,46.75) 6.1,46.53 ; v1(6.1,46.75) 6.32,46.75 ; v1(6.1,46.75) 5.84,46.75 ; 34.6,41.18 v1(34.6,41.4) ; v1(34.6,41.4) 34.6,41.65 ; v1(34.6,41.4) 34.8,41.4 ; v1(34.6,41.4) 34.38,41.4 ; 26.4,5.82 v1(26.4,6.05) ; v1(26.4,6.05) 26.72,6.05 ; v1(26.4,6.05) 26.4,6.3 ; v1(26.4,6.05) 26.17,6.05 ; v1(8.9,46.2) 8.9,46.5 ; v1(8.9,46.2) 8.65,46.2 ; v1(8.9,46.2) 8.9,45.95 ; v1(8.9,46.2) 9.17,46.2 ; v1(35,72.8) 35,73.03 ; v1(35,72.8) 34.66,72.8 ; v1(35,72.8) 35,72.6 ; v1(35,72.8) 35.2,72.8 ; v1(21,8.1) 21.29,8.1 ; v1(21,8.1) 21,7.83 ; v1(21,8.1) 21,8.25 ; v1(21,8.1) 20.85,8.1 ; v1(18.05,33.25) 18.05,33.41 ; v1(18.05,33.25) 17.88,33.25 ; v1(18.05,33.25) 18.21,33.25 ; v1(18.05,33.25) 18.05,33.02 ; v1(24.2,16.35) 24.36,16.35 ; v1(24.2,16.35) 24.01,16.35 ; v1(24.2,16.35) 24.2,16.51 ; v1(24.2,16.35) 24.2,15.98 ; 26.83,23.7 v1(27,23.7) ; v1(27,23.7) 27.19,23.7 ; v1(27,23.7) 27,23.87 ; v1(27,23.7) 27,23.33 ; v1(10.9,38.6) 10.9,38.8 ; v1(10.9,38.6) 10.9,38.35 ; v1(10.9,38.6) 11.1,38.6 ; v1(10.9,38.6) 10.62,38.6 ; 32.73,75.3 v1(32.95,75.3) ; v1(32.95,75.3) 32.95,75.08 ; v1(32.95,75.3) 32.95,75.64 ; v1(32.95,75.3) 33.18,75.3 ; v1(13.9,53.6) 14.26,53.6 ; v1(13.9,53.6) 13.74,53.6 ; v1(13.9,53.6) 13.9,53.4 ; v1(13.9,53.6) 13.9,53.76 ; 9.7,39.49 v1(9.7,39.65) ; v1(9.7,39.65) 9.54,39.65 ; v1(9.7,39.65) 9.97,39.65 ; v1(9.7,39.65) 9.7,39.94 ; 35.54,82.1 v1(35.87,82.1) ; v1(35.87,82.1) 36.02,82.1 ; v1(35.87,82.1) 35.87,81.96 ; v1(35.87,82.1) 35.87,82.33 ; v1(33.8,20.3) 33.98,20.3 ; v1(33.8,20.3) 33.8,19.92 ; v1(33.8,20.3) 33.61,20.3 ; v1(33.8,20.3) 33.8,20.49 ; v1(30.95,14.55) 30.95,14.81 ; v1(30.95,14.55) 30.95,14.28 ; v1(30.95,14.55) 30.69,14.55 ; v1(30.95,14.55) 31.25,14.55 ; 14.01,44.8 v1(14.35,44.8) ; v1(14.35,44.8) 14.56,44.8 ; v1(14.35,44.8) 14.35,45.03 ; v1(14.35,44.8) 14.35,44.59 ; v1(12.7,48.2) 12.7,48.37 ; v1(12.7,48.2) 12.31,48.2 ; v1(12.7,48.2) 12.86,48.2 ; v1(12.7,48.2) 12.7,48.04 ; v1(17.21,81.55) 17.36,81.55 ; v1(17.21,81.55) 17.21,81.76 ; v1(17.21,81.55) 17.21,81.4 ; v1(17.21,81.55) 16.86,81.55 ; v1(31.85,36.9) 31.85,37.14 ; v1(31.85,36.9) 31.85,36.64 ; v1(31.85,36.9) 31.55,36.9 ; v1(31.85,36.9) 32.09,36.9 ; 10.93,77.38 v1(11.13,77.38) ; v1(11.13,77.38) 11.13,77.58 ; v1(11.13,77.38) 11.13,77.1 ; v1(11.13,77.38) 11.41,77.38 ; v1(10.5,63.75) 10.5,63.94 ; v1(10.5,63.75) 10.33,63.75 ; v1(10.5,63.75) 10.5,63.58 ; v1(10.5,63.75) 10.88,63.75 ; v1(15.4,56.75) 15.4,56.96 ; v1(15.4,56.75) 15.64,56.75 ; v1(15.4,56.75) 15.4,56.55 ; v1(15.4,56.75) 15.19,56.75 ; 7.4,41.23 v1(7.4,41.38) ; v1(7.4,41.38) 7.74,41.38 ; v1(7.4,41.38) 7.25,41.38 ; v1(7.4,41.38) 7.4,41.6 ; v1(34.4,15.05) 34.4,15.36 ; v1(34.4,15.05) 34.4,14.86 ; v1(34.4,15.05) 34.14,15.05 ; v1(34.4,15.05) 34.59,15.05 ; 40.35,25.91 v1(40.35,26.1) ; v1(40.35,26.1) 40.35,26.38 ; v1(40.35,26.1) 40.54,26.1 ; v1(40.35,26.1) 40.06,26.1 ; 11.25,35.84 v1(11.25,36.05) ; v1(11.25,36.05) 11.45,36.05 ; v1(11.25,36.05) 11,36.05 ; v1(11.25,36.05) 11.25,36.25 ; v1(31.52,81.25) 31.77,81.25 ; v1(31.52,81.25) 31.3,81.25 ; v1(31.52,81.25) 31.52,81.03 ; v1(31.52,81.25) 31.52,81.57 ; 25.73,60.8 v1(25.87,60.8) ; v1(25.87,60.8) 25.87,60.65 ; v1(25.87,60.8) 25.87,60.98 ; v1(25.87,60.8) 26.03,60.8 ; v1(32.4,14.25) 32.65,14.25 ; v1(32.4,14.25) 32.4,14.53 ; v1(32.4,14.25) 32.12,14.25 ; v1(32.4,14.25) 32.4,14 ; 16.05,26.5 v1(16.25,26.5) ; v1(16.25,26.5) 16.25,26.7 ; v1(16.25,26.5) 16.25,26.16 ; v1(16.25,26.5) 16.47,26.5 ; 28.1,12.04 v1(28.1,12.3) ; v1(28.1,12.3) 28.41,12.3 ; v1(28.1,12.3) 28.1,12.52 ; v1(28.1,12.3) 27.88,12.3 ; 37.49,57.55 v1(37.8,57.55) ; v1(37.8,57.55) 37.8,57.3 ; v1(37.8,57.55) 38.03,57.55 ; v1(37.8,57.55) 37.8,57.78 ; 37.15,22.23 v1(37.15,22.5) ; v1(37.15,22.5) 36.94,22.5 ; v1(37.15,22.5) 37.15,22.71 ; v1(37.15,22.5) 37.44,22.5 ; v1(38.05,68.1) 38.05,68.28 ; v1(38.05,68.1) 38.05,67.73 ; v1(38.05,68.1) 38.23,68.1 ; v1(38.05,68.1) 37.86,68.1 ; 11,31.55 v1(11.25,31.55) ; v1(11.25,31.55) 11.25,31.72 ; v1(11.25,31.55) 11.25,31.31 ; v1(11.25,31.55) 11.42,31.55 ; 4.67,61.5 v1(4.9,61.5) ; v1(4.9,61.5) 4.9,61.26 ; v1(4.9,61.5) 5.23,61.5 ; v1(4.9,61.5) 4.9,61.7 ; 11,22.95 v1(11.2,22.95) ; v1(11.2,22.95) 11.2,22.78 ; v1(11.2,22.95) 11.2,23.29 ; v1(11.2,22.95) 11.37,22.95 ; v1(14.85,54.55) 14.85,54.71 ; v1(14.85,54.55) 14.85,54.15 ; v1(14.85,54.55) 15.01,54.55 ; v1(14.85,54.55) 14.69,54.55 ; 11.2,18.82 v1(11.2,19.15) ; v1(11.2,19.15) 11,19.15 ; v1(11.2,19.15) 11.2,19.33 ; v1(11.2,19.15) 11.38,19.15 ; 23.64,18.25 v1(23.85,18.25) ; v1(23.85,18.25) 23.85,17.99 ; v1(23.85,18.25) 24.16,18.25 ; v1(23.85,18.25) 23.85,18.46 ; 24.5,55.25 v1(24.75,55.25) ; v1(24.75,55.25) 24.75,55.56 ; v1(24.75,55.25) 25.01,55.25 ; v1(24.75,55.25) 24.75,55 ; 13.45,14.25 v1(13.8,14.25) ; v1(13.8,14.25) 13.8,14.06 ; v1(13.8,14.25) 13.99,14.25 ; v1(13.8,14.25) 13.8,14.46 ; v1(12.85,53.6) 13.13,53.6 ; v1(12.85,53.6) 12.61,53.6 ; v1(12.85,53.6) 12.85,53.31 ; v1(12.85,53.6) 12.85,53.84 ; v1(34.55,36.85) 34.55,37.08 ; v1(34.55,36.85) 34.55,36.71 ; v1(34.55,36.85) 34.41,36.85 ; v1(34.55,36.85) 34.8,36.85 ; v1(26.2,23.35) 26.41,23.35 ; v1(26.2,23.35) 25.92,23.35 ; v1(26.2,23.35) 26.2,23.07 ; v1(26.2,23.35) 26.2,23.56 ; 30.12,82.43 v1(30.12,82.77) ; v1(30.12,82.77) 30.34,82.77 ; v1(30.12,82.77) 30.12,82.98 ; v1(30.12,82.77) 29.9,82.77 ; v1(11.83,64.29) 11.83,64.52 ; v1(11.83,64.29) 11.49,64.29 ; v1(11.83,64.29) 11.99,64.29 ; v1(11.83,64.29) 11.83,64.13 ; v1(19.1,4.9) 19.1,5.2 ; v1(19.1,4.9) 19.34,4.9 ; v1(19.1,4.9) 18.84,4.9 ; v1(19.1,4.9) 19.1,4.66 ; v1(19.27,16) 19.27,16.14 ; v1(19.27,16) 19.27,15.78 ; v1(19.27,16) 19.13,16 ; v1(19.27,16) 19.62,16 ; 10.8,72.34 v1(10.8,72.5) ; v1(10.8,72.5) 11.14,72.5 ; v1(10.8,72.5) 10.8,72.72 ; v1(10.8,72.5) 10.63,72.5 ; v1(14.25,79.35) 14.53,79.35 ; v1(14.25,79.35) 14.25,79.07 ; v1(14.25,79.35) 14.25,79.57 ; v1(14.25,79.35) 14.03,79.35 ; 13.46,38 v1(13.7,38) ; v1(13.7,38) 13.7,37.76 ; v1(13.7,38) 13.7,38.29 ; v1(13.7,38) 13.9,38 ; 23.9,26.43 v1(23.9,26.6) ; v1(23.9,26.6) 23.9,26.79 ; v1(23.9,26.6) 23.73,26.6 ; v1(23.9,26.6) 24.07,26.6 ; v1(32.9,6.85) 33.17,6.85 ; v1(32.9,6.85) 32.73,6.85 ; v1(32.9,6.85) 32.9,6.68 ; v1(32.9,6.85) 32.9,7.14 ; 11,50.3 v1(11,50.45) ; v1(11,50.45) 11.15,50.45 ; v1(11,50.45) 11,50.64 ; v1(11,50.45) 10.62,50.45 ; v1(41.9,73.1) 42.2,73.1 ; v1(41.9,73.1) 41.72,73.1 ; v1(41.9,73.1) 41.9,73.28 ; v1(41.9,73.1) 41.9,72.91 ; v1(23.35,54.4) 23.35,54.69 ; v1(23.35,54.4) 23.59,54.4 ; v1(23.35,54.4) 23.08,54.4 ; v1(23.35,54.4) 23.35,54.16 ; 11.48,46.25 v1(11.8,46.25) ; v1(11.8,46.25) 11.8,46.45 ; v1(11.8,46.25) 11.99,46.25 ; v1(11.8,46.25) 11.8,46 ; v1(37,29) 37,29.16 ; v1(37,29) 37.16,29 ; v1(37,29) 37,28.78 ; v1(37,29) 36.66,29 ; 27.89,50.15 v1(28.1,50.15) ; v1(28.1,50.15) 28.39,50.15 ; v1(28.1,50.15) 28.1,49.94 ; v1(28.1,50.15) 28.1,50.42 ; v1(28.4,14.85) 28.69,14.85 ; v1(28.4,14.85) 28.4,14.57 ; v1(28.4,14.85) 28.4,15.05 ; v1(28.4,14.85) 28.16,14.85 ; v1(17.4,15.8) 17.4,15.95 ; v1(17.4,15.8) 17.23,15.8 ; v1(17.4,15.8) 17.4,15.4 ; v1(17.4,15.8) 17.55,15.8 ; 37.2,25 v1(37.6,25) ; v1(37.6,25) 37.6,24.85 ; v1(37.6,25) 37.6,25.17 ; v1(37.6,25) 37.75,25 ; v1(10.91,74.15) 10.91,74.48 ; v1(10.91,74.15) 11.1,74.15 ; v1(10.91,74.15) 10.68,74.15 ; v1(10.91,74.15) 10.91,73.97 ; J6.2 39.65,76.86 ; J6.2 39.26,76.86 ; J6.2 39.5,77.01 ; J6.2 39.5,76.53 ; v1(29,82.15) 29,82.42 ; v1(29,82.15) 29.27,82.15 ; v1(29,82.15) 28.8,82.15 ; v1(29,82.15) 29,81.87 ; 12.31,57.25 v1(12.65,57.25) ; v1(12.65,57.25) 12.65,57.47 ; v1(12.65,57.25) 12.86,57.25 ; v1(12.65,57.25) 12.65,57.04 ; v1(10,46.2) 10,46.47 ; v1(10,46.2) 10.3,46.2 ; v1(10,46.2) 9.78,46.2 ; v1(10,46.2) 10,45.98 ; 17.47,78.67 v1(17.62,78.67) ; v1(17.62,78.67) 17.62,78.98 ; v1(17.62,78.67) 17.88,78.67 ; v1(17.62,78.67) 17.62,78.52 ; 15.15,74.81 v1(15.15,75) ; v1(15.15,75) 15.34,75 ; v1(15.15,75) 14.92,75 ; v1(15.15,75) 15.15,75.34 ; 17.23,8.2 v1(17.4,8.2) ; v1(17.4,8.2) 17.55,8.2 ; v1(17.4,8.2) 17.4,8.6 ; v1(17.4,8.2) 17.4,8.05 ; v1(14.2,78.15) 14.2,78.39 ; v1(14.2,78.15) 14.04,78.15 ; v1(14.2,78.15) 14.2,77.99 ; v1(14.2,78.15) 14.53,78.15 ; 9.51,43.15 v1(9.8,43.15) ; v1(9.8,43.15) 9.8,43 ; v1(9.8,43.15) 9.8,43.35 ; v1(9.8,43.15) 10,43.15 ; 40.05,74.25 v1(40.2,74.25) ; v1(40.2,74.25) 40.2,74.05 ; v1(40.2,74.25) 40.2,74.4 ; v1(40.2,74.25) 40.56,74.25 ; v1(33.8,24.05) 33.97,24.05 ; v1(33.8,24.05) 33.8,23.88 ; v1(33.8,24.05) 33.8,24.45 ; v1(33.8,24.05) 33.63,24.05 ; 15.45,54.18 v1(15.45,54.4) ; v1(15.45,54.4) 15.16,54.4 ; v1(15.45,54.4) 15.67,54.4 ; v1(15.45,54.4) 15.45,54.67 ; 40.14,28.85 v1(40.3,28.85) ; v1(40.3,28.85) 40.47,28.85 ; v1(40.3,28.85) 40.3,29.2 ; v1(40.3,28.85) 40.3,28.69 ; v1(13.65,82.65) 13.65,82.93 ; v1(13.65,82.65) 13.5,82.65 ; v1(13.65,82.65) 13.94,82.65 ; v1(13.65,82.65) 13.65,82.5 ; 12.05,73.97 v1(12.05,74.15) ; v1(12.05,74.15) 11.81,74.15 ; v1(12.05,74.15) 12.05,74.48 ; v1(12.05,74.15) 12.23,74.15 ; v1(34.6,35.85) 34.6,35.99 ; v1(34.6,35.85) 34.8,35.85 ; v1(34.6,35.85) 34.6,35.52 ; v1(34.6,35.85) 34.46,35.85 ; v1(25.85,56.4) 26.16,56.4 ; v1(25.85,56.4) 25.85,56.66 ; v1(25.85,56.4) 25.85,56.15 ; v1(25.85,56.4) 25.6,56.4 ; 5,49.39 v1(5,49.67) ; v1(5,49.67) 4.72,49.67 ; v1(5,49.67) 5,49.85 ; v1(5,49.67) 5.18,49.67 ; 16.95,25.7 v1(17.1,25.7) ; v1(17.1,25.7) 17.1,25.31 ; v1(17.1,25.7) 17.1,25.85 ; v1(17.1,25.7) 17.27,25.7 ; 12.55,69.45 v1(12.55,69.7) ; v1(12.55,69.7) 12.87,69.7 ; v1(12.55,69.7) 12.55,69.95 ; v1(12.55,69.7) 12.3,69.7 ; v1(31.77,82.77) 31.77,82.95 ; v1(31.77,82.77) 31.77,82.47 ; v1(31.77,82.77) 32.04,82.77 ; v1(31.77,82.77) 31.6,82.77 ; 12.57,50.2 v1(12.57,50.57) ; v1(12.57,50.57) 12.57,50.74 ; v1(12.57,50.57) 12.76,50.57 ; v1(12.57,50.57) 12.41,50.57 ; 33.25,25.03 v1(33.25,25.4) ; v1(33.25,25.4) 33.25,25.56 ; v1(33.25,25.4) 33.41,25.4 ; v1(33.25,25.4) 33.06,25.4 ; 27.1,51.12 v1(27.3,51.12) ; v1(27.3,51.12) 27.3,51.31 ; v1(27.3,51.12) 27.3,50.76 ; v1(27.3,51.12) 27.48,51.12 ; 33.53,25.85 v1(33.75,25.85) ; v1(33.75,25.85) 33.75,25.63 ; v1(33.75,25.85) 34.07,25.85 ; v1(33.75,25.85) 33.75,26.09 ; 28.83,36.45 v1(28.97,36.45) ; v1(28.97,36.45) 28.97,36.11 ; v1(28.97,36.45) 28.97,36.59 ; v1(28.97,36.45) 29.15,36.45 ; v1(40.35,24.4) 40.35,24.68 ; v1(40.35,24.4) 40.35,24.21 ; v1(40.35,24.4) 40.07,24.4 ; v1(40.35,24.4) 40.54,24.4 ; v1(7.5,42.1) 7.5,42.26 ; v1(7.5,42.1) 7.33,42.1 ; v1(7.5,42.1) 7.5,41.7 ; v1(7.5,42.1) 7.66,42.1 ; 11.3,32.49 v1(11.3,32.65) ; v1(11.3,32.65) 11,32.65 ; v1(11.3,32.65) 11.3,32.8 ; v1(11.3,32.65) 11.45,32.65 ; 14.29,82.42 v1(14.67,82.42) ; v1(14.67,82.42) 14.67,82.25 ; v1(14.67,82.42) 14.85,82.42 ; v1(14.67,82.42) 14.67,82.6 ; v1(9.15,42) 9.46,42 ; v1(9.15,42) 9.15,42.22 ; v1(9.15,42) 8.93,42 ; v1(9.15,42) 9.15,41.74 ; v1(30.4,13.85) 30.56,13.85 ; v1(30.4,13.85) 30.25,13.85 ; v1(30.4,13.85) 30.4,14.26 ; v1(30.4,13.85) 30.4,13.7 ; 12.05,13.95 v1(12.3,13.95) ; v1(12.3,13.95) 12.56,13.95 ; v1(12.3,13.95) 12.3,13.7 ; v1(12.3,13.95) 12.3,14.26 ; v1(38.9,64.85) 38.9,65.17 ; v1(38.9,64.85) 38.9,64.62 ; v1(38.9,64.85) 39.13,64.85 ; v1(38.9,64.85) 38.65,64.85 ; 18.56,12.6 v1(18.85,12.6) ; v1(18.85,12.6) 18.85,12.32 ; v1(18.85,12.6) 18.85,12.81 ; v1(18.85,12.6) 19.06,12.6 ; 23.4,50.82 v1(23.4,51.1) ; v1(23.4,51.1) 23.12,51.1 ; v1(23.4,51.1) 23.55,51.1 ; v1(23.4,51.1) 23.4,51.25 ; v1(11.75,56.4) 12.01,56.4 ; v1(11.75,56.4) 11.75,56.68 ; v1(11.75,56.4) 11.46,56.4 ; v1(11.75,56.4) 11.75,56.23 ; v1(30,48.2) 30.25,48.2 ; v1(30,48.2) 30,48.36 ; v1(30,48.2) 29.84,48.2 ; v1(30,48.2) 30,48.04 ; 26.45,14.27 v1(26.45,14.65) ; v1(26.45,14.65) 26.45,14.82 ; v1(26.45,14.65) 26.62,14.65 ; v1(26.45,14.65) 26.27,14.65 ; v1(19.65,14.65) 19.65,14.82 ; v1(19.65,14.65) 19.84,14.65 ; v1(19.65,14.65) 19.65,14.27 ; v1(19.65,14.65) 19.48,14.65 ; v1(24.45,7.45) 24.45,7.74 ; v1(24.45,7.45) 24.21,7.45 ; v1(24.45,7.45) 24.45,7.21 ; v1(24.45,7.45) 24.72,7.45 ; 15.16,78.72 v1(15.5,78.72) ; v1(15.5,78.72) 15.67,78.72 ; v1(15.5,78.72) 15.5,78.95 ; v1(15.5,78.72) 15.5,78.55
  BOTTOM w0.15: v1(8.45,40.65) 8.75,40.65 ; v1(8.45,40.65) 8.45,40.92 ; v1(8.45,40.65) 8.22,40.65 ; v1(8.45,40.65) 8.45,40.42 ; 13.3,57.08 v1(13.3,57.25) ; v1(13.3,57.25) 13.3,57.63 ; v1(13.3,57.25) 13.12,57.25 ; v1(13.3,57.25) 13.47,57.25 ; 35.07,77.16 v1(35.07,77.47) ; v1(35.07,77.47) 35.32,77.47 ; v1(35.07,77.47) 34.83,77.47 ; v1(35.07,77.47) 35.07,77.72 ; v1(26.45,14.65) 26.45,14.79 ; v1(26.45,14.65) 26.45,14.5 ; v1(26.45,14.65) 26.31,14.65 ; v1(26.45,14.65) 26.87,14.65 ; v1(15.27,61.51) 15.27,61.88 ; v1(15.27,61.51) 15.27,61.32 ; v1(15.27,61.51) 15.08,61.51 ; v1(15.27,61.51) 15.47,61.51 ; v1(11.3,33.9) 11.3,34.15 ; v1(11.3,33.9) 11.58,33.9 ; v1(11.3,33.9) 11.05,33.9 ; v1(11.3,33.9) 11.3,33.61 ; 16.4,30.21 v1(16.4,30.35) ; v1(16.4,30.35) 16.55,30.35 ; v1(16.4,30.35) 16.26,30.35 ; v1(16.4,30.35) 16.4,30.76 ; v1(39.4,20.05) 39.57,20.05 ; v1(39.4,20.05) 39.4,19.82 ; v1(39.4,20.05) 39.06,20.05 ; v1(39.4,20.05) 39.4,20.22 ; 8.87,40.2 v1(9.05,40.2) ; v1(9.05,40.2) 9.24,40.2 ; v1(9.05,40.2) 9.05,39.82 ; v1(9.05,40.2) 9.05,40.38 ; v1(27.8,58.25) 27.8,58.41 ; v1(27.8,58.25) 27.48,58.25 ; v1(27.8,58.25) 27.96,58.25 ; v1(27.8,58.25) 27.8,58 ; 13.04,60.15 v1(13.35,60.15) ; v1(13.35,60.15) 13.35,59.96 ; v1(13.35,60.15) 13.54,60.15 ; v1(13.35,60.15) 13.35,60.41 ; v1(32.57,62.45) 32.57,62.68 ; v1(32.57,62.45) 32.57,62.21 ; v1(32.57,62.45) 32.81,62.45 ; v1(32.57,62.45) 32.25,62.45 ; v1(27.75,31.1) 27.95,31.1 ; v1(27.75,31.1) 27.75,31.3 ; v1(27.75,31.1) 27.75,30.8 ; v1(27.75,31.1) 27.52,31.1 ; 37.63,76.86 v1(37.91,76.86) ; v1(37.91,76.86) J6.2 ; v1(37.91,76.86) 37.91,76.6 ; v1(37.91,76.86) 37.91,77.14 ; 4.63,50.67 v1(4.82,50.67) ; v1(4.82,50.67) 4.82,50.3 ; v1(4.82,50.67) 4.98,50.67 ; v1(4.82,50.67) 4.82,50.83 ; 30.65,30.1 v1(30.85,30.1) ; v1(30.85,30.1) 30.85,29.94 ; v1(30.85,30.1) 31.01,30.1 ; v1(30.85,30.1) 30.85,30.47 ; v1(11.2,19.15) 11.2,19.34 ; v1(11.2,19.15) 11.57,19.15 ; v1(11.2,19.15) 11.05,19.15 ; v1(11.2,19.15) 11.2,19 ; v1(27.2,13) 27.2,13.19 ; v1(27.2,13) 27.2,12.71 ; v1(27.2,13) 27.39,13 ; v1(27.2,13) 26.92,13 ; v1(10.95,60.75) 11.31,60.75 ; v1(10.95,60.75) 10.75,60.75 ; v1(10.95,60.75) 10.95,60.95 ; v1(10.95,60.75) 10.95,60.55 ; v1(17.55,18.15) 17.55,18.31 ; v1(17.55,18.15) 17.71,18.15 ; v1(17.55,18.15) 17.36,18.15 ; v1(17.55,18.15) 17.55,17.77 ; 21.8,52.52 v1(22.1,52.52) ; v1(22.1,52.52) 22.32,52.52 ; v1(22.1,52.52) 22.1,52.79 ; v1(22.1,52.52) 22.1,52.3 ; 41.65,78.5 v1(41.85,78.5) ; v1(41.85,78.5) 42.07,78.5 ; v1(41.85,78.5) 41.85,78.3 ; v1(41.85,78.5) 41.85,78.84 ; v1(39.85,20.65) 39.85,20.84 ; v1(39.85,20.65) 39.66,20.65 ; v1(39.85,20.65) 39.85,20.33 ; v1(39.85,20.65) 40.1,20.65 ; 6.8,41.53 v1(6.8,41.9) ; v1(6.8,41.9) 6.61,41.9 ; v1(6.8,41.9) 6.97,41.9 ; v1(6.8,41.9) 6.8,42.07 ; v1(33.15,14.4) 33.15,14.59 ; v1(33.15,14.4) 32.85,14.4 ; v1(33.15,14.4) 33.34,14.4 ; v1(33.15,14.4) 33.15,14.14 ; 30.85,35.6 v1(30.85,35.75) ; v1(30.85,35.75) 30.66,35.75 ; v1(30.85,35.75) 30.85,36.12 ; v1(30.85,35.75) 31,35.75 ; TP4.1 32.3,47.68 ; TP4.1 32.3,47.23 ; TP4.1 32.04,47.38 ; TP4.1 32.45,47.38 ; 34.26,39.5 v1(34.6,39.5) ; v1(34.6,39.5) 34.6,39.73 ; v1(34.6,39.5) 34.75,39.5 ; v1(34.6,39.5) 34.6,39.35 ; 37,28.84 v1(37,29) ; v1(37,29) 37.26,29 ; v1(37,29) 37,29.2 ; v1(37,29) 36.84,29 ; 22.91,52.55 v1(23.15,52.55) ; v1(23.15,52.55) 23.15,52.79 ; v1(23.15,52.55) 23.15,52.31 ; v1(23.15,52.55) 23.47,52.55 ; v1(28.87,77.45) 28.87,77.7 ; v1(28.87,77.45) 28.87,77.18 ; v1(28.87,77.45) 29.12,77.45 ; v1(28.87,77.45) 28.58,77.45 ; 40.4,22.05 v1(40.4,22.35) ; v1(40.4,22.35) 40.23,22.35 ; v1(40.4,22.35) 40.4,22.52 ; v1(40.4,22.35) 40.65,22.35 ; 16.12,32.75 v1(16.4,32.75) ; v1(16.4,32.75) 16.69,32.75 ; v1(16.4,32.75) 16.4,33.03 ; v1(16.4,32.75) 16.4,32.47 ; v1(19.5,51.05) 19.72,51.05 ; v1(19.5,51.05) 19.32,51.05 ; v1(19.5,51.05) 19.5,51.4 ; v1(19.5,51.05) 19.5,50.87 ; 11.5,12.48 v1(11.5,12.7) ; v1(11.5,12.7) 11.5,12.85 ; v1(11.5,12.7) 11.35,12.7 ; v1(11.5,12.7) 11.85,12.7 ; v1(12,72.9) 12.15,72.9 ; v1(12,72.9) 12,72.75 ; v1(12,72.9) 12,73.07 ; v1(12,72.9) 11.61,72.9 ; 12.46,62.46 v1(12.46,62.74) ; v1(12.46,62.74) 12.46,63 ; v1(12.46,62.74) 12.71,62.74 ; v1(12.46,62.74) 12.18,62.74 ; v1(27.7,33.25) 27.94,33.25 ; v1(27.7,33.25) 27.7,33.58 ; v1(27.7,33.25) 27.52,33.25 ; v1(27.7,33.25) 27.7,33.05 ; v1(14.1,44.05) 14.1,44.3 ; v1(14.1,44.05) 13.87,44.05 ; v1(14.1,44.05) 14.41,44.05 ; v1(14.1,44.05) 14.1,43.82 ; 7.96,42.12 v1(8.22,42.12) ; v1(8.22,42.12) 8.22,42.34 ; v1(8.22,42.12) 8.22,41.82 ; v1(8.22,42.12) 8.44,42.12 ; v1(18.1,16.25) 18.29,16.25 ; v1(18.1,16.25) 18.1,16.06 ; v1(18.1,16.25) 18.1,16.62 ; v1(18.1,16.25) 17.91,16.25 ; v1(16.77,80.03) 16.77,80.18 ; v1(16.77,80.03) 16.45,80.03 ; v1(16.77,80.03) 16.77,79.78 ; v1(16.77,80.03) 16.92,80.03 ; v1(13.35,61.9) 13.56,61.9 ; v1(13.35,61.9) 13.03,61.9 ; v1(13.35,61.9) 13.35,62.11 ; v1(13.35,61.9) 13.35,61.65 ; v1(40.4,23.4) 40.65,23.4 ; v1(40.4,23.4) 40.4,23.18 ; v1(40.4,23.4) 40.18,23.4 ; v1(40.4,23.4) 40.4,23.65 ; J6.2 39.5,76.69 ; J6.2 39.5,77.06 ; J6.2 39.87,76.86 ; 18.05,33.08 v1(18.05,33.25) ; v1(18.05,33.25) 18.05,33.54 ; v1(18.05,33.25) 17.88,33.25 ; v1(18.05,33.25) 18.3,33.25 ; 16.19,52.05 v1(16.45,52.05) ; v1(16.45,52.05) 16.45,51.74 ; v1(16.45,52.05) 16.62,52.05 ; v1(16.45,52.05) 16.45,52.22 ; 11.13,32.65 v1(11.3,32.65) ; v1(11.3,32.65) 11.3,33.02 ; v1(11.3,32.65) 11.5,32.65 ; v1(11.3,32.65) 11.3,32.48 ; 5.94,49.72 v1(5.94,50.09) ; v1(5.94,50.09) 5.94,50.28 ; v1(5.94,50.09) 5.74,50.09 ; v1(5.94,50.09) 6.14,50.09 ; v1(33.97,77.45) 34.21,77.45 ; v1(33.97,77.45) 33.97,77.19 ; v1(33.97,77.45) 33.67,77.45 ; v1(33.97,77.45) 33.97,77.69 ; v1(27,23.7) 26.9,23.8 J8.7 ; v1(12.7,48.2) 12.7,48.56 ; v1(12.7,48.2) 12.55,48.2 ; v1(12.7,48.2) 12.7,48.05 ; v1(12.7,48.2) 12.91,48.2 ; 9.8,44.73 v1(9.8,44.95) ; v1(9.8,44.95) 10.14,44.95 ; v1(9.8,44.95) 9.8,45.09 ; v1(9.8,44.95) 9.66,44.95 ; v1(29.35,46.35) 29.35,46.54 ; v1(29.35,46.35) 29.35,46.11 ; v1(29.35,46.35) 29.16,46.35 ; v1(29.35,46.35) 29.67,46.35 ; 33.7,7.33 v1(33.7,7.6) ; v1(33.7,7.6) 33.4,7.6 ; v1(33.7,7.6) 33.92,7.6 ; v1(33.7,7.6) 33.7,7.82 ; 30.25,60.48 v1(30.25,60.7) ; v1(30.25,60.7) 30.03,60.7 ; v1(30.25,60.7) 30.5,60.7 ; v1(30.25,60.7) 30.25,60.98 ; v1(6.3,47.45) 6.5,47.45 ; v1(6.3,47.45) 6.3,47.66 ; v1(6.3,47.45) 6.3,47.25 ; v1(6.3,47.45) 5.95,47.45 ; v1(18.1,28.7) 18.1,29.07 ; v1(18.1,28.7) 17.91,28.7 ; v1(18.1,28.7) 18.3,28.7 ; v1(18.1,28.7) 18.1,28.51 ; v1(24.2,16.35) 24.6,16.35 ; v1(24.2,16.35) 24.05,16.35 ; v1(24.2,16.35) 24.2,16.5 ; v1(24.2,16.35) 24.2,16.19 ; 28.9,41.57 v1(28.9,41.8) ; v1(28.9,41.8) 29.13,41.8 ; v1(28.9,41.8) 28.9,42.03 ; v1(28.9,41.8) 28.57,41.8 ; v1(28.55,8.25) 28.74,8.25 ; v1(28.55,8.25) 28.39,8.25 ; v1(28.55,8.25) 28.55,7.88 ; v1(28.55,8.25) 28.55,8.41 ; 11.63,75.77 J3.5 ; J3.5 12.13,75.77 ; J3.5 11.86,76 ; J3.5 11.86,75.48 ; v1(20.45,5.65) 20.59,5.65 ; v1(20.45,5.65) 20.14,5.65 ; v1(20.45,5.65) 20.45,5.79 ; v1(20.45,5.65) 20.45,5.4 ; v1(39.3,69.2) 39.3,69.5 ; v1(39.3,69.2) 39.56,69.2 ; v1(39.3,69.2) 39.3,68.97 ; v1(39.3,69.2) 39.07,69.2 ; 18.7,23.45 v1(19.05,23.45) ; v1(19.05,23.45) 19.05,23.23 ; v1(19.05,23.45) 19.05,23.6 ; v1(19.05,23.45) 19.2,23.45 ; v1(25.75,51.05) 25.75,51.4 ; v1(25.75,51.05) 25.75,50.86 ; v1(25.75,51.05) 25.94,51.05 ; v1(25.75,51.05) 25.54,51.05 ; 32.27,18.35 v1(32.45,18.35) ; v1(32.45,18.35) 32.45,18.53 ; v1(32.45,18.35) 32.45,18.12 ; v1(32.45,18.35) 32.78,18.35 ; v1(38.5,19.2) 38.5,19.42 ; v1(38.5,19.2) 38.5,18.92 ; v1(38.5,19.2) 38.72,19.2 ; v1(38.5,19.2) 38.21,19.2 ; v1(13.35,53.9) 13.35,54.19 ; v1(13.35,53.9) 13.51,53.9 ; v1(13.35,53.9) 13.35,53.74 ; v1(13.35,53.9) 13.07,53.9 ; 10.55,69.55 v1(10.85,69.55) ; v1(10.85,69.55) 11,69.55 ; v1(10.85,69.55) 10.85,69.34 ; v1(10.85,69.55) 10.85,69.7 ; 6.33,46.15 v1(6.5,46.15) ; v1(6.5,46.15) 6.68,46.15 ; v1(6.5,46.15) 6.5,45.76 ; v1(6.5,46.15) 6.5,46.32 ; 32.25,78.86 v1(32.25,79.12) ; v1(32.25,79.12) 32.25,79.41 ; v1(32.25,79.12) 31.97,79.12 ; v1(32.25,79.12) 32.52,79.12 ; 15.52,81.99 v1(15.52,82.33) ; v1(15.52,82.33) 15.76,82.33 ; v1(15.52,82.33) 15.35,82.33 ; v1(15.52,82.33) 15.52,82.5 ; 5,49.53 v1(5,49.67) ; v1(5,49.67) 4.85,49.67 ; v1(5,49.67) 5.33,49.67 ; v1(5,49.67) 5,49.91 ; v1(19.65,15.5) 19.65,15.64 ; v1(19.65,15.5) 19.24,15.5 ; v1(19.65,15.5) 19.79,15.5 ; v1(19.65,15.5) 19.65,15.35 ; U2.8 28.28,48.3 ; U2.8 28.57,48.02 ; U2.8 28,48.02 ; U2.8 28.28,47.74 ; v1(28.85,10.15) 28.85,10.4 ; v1(28.85,10.15) 29.1,10.15 ; v1(28.85,10.15) 28.85,9.84 ; v1(28.85,10.15) 28.6,10.15 ; v1(16.9,15.25) 16.9,15.42 ; v1(16.9,15.25) 16.73,15.25 ; v1(16.9,15.25) 16.9,15 ; v1(16.9,15.25) 17.22,15.25 ; v1(11.25,31.55) 11.25,31.84 ; v1(11.25,31.55) 11.1,31.55 ; v1(11.25,31.55) 11.25,31.4 ; v1(11.25,31.55) 11.53,31.55 ; 34.24,42.35 v1(34.6,42.35) ; v1(34.6,42.35) 34.77,42.35 ; v1(34.6,42.35) 34.6,42.18 ; v1(34.6,42.35) 34.6,42.55 ; 38.54,25.75 v1(38.75,25.75) ; v1(38.75,25.75) 38.75,25.39 ; v1(38.75,25.75) 38.75,25.96 ; v1(38.75,25.75) 38.96,25.75 ; 23.2,26.25 v1(23.2,26.6) ; v1(23.2,26.6) 23.4,26.6 ; v1(23.2,26.6) 22.98,26.6 ; v1(23.2,26.6) 23.2,26.79 ; v1(8.85,42.6) 9,42.6 ; v1(8.85,42.6) 8.53,42.6 ; v1(8.85,42.6) 8.85,42.45 ; v1(8.85,42.6) 8.85,42.85 ; v1(4.8,51.65) 4.8,51.97 ; v1(4.8,51.65) 4.8,51.42 ; v1(4.8,51.65) 5.04,51.65 ; v1(4.8,51.65) 4.6,51.65 ; v1(37.6,25) 37.6,25.38 ; v1(37.6,25) 37.45,25 ; v1(37.6,25) 37.6,24.85 ; v1(37.6,25) 37.79,25 ; v1(27.1,58.8) 27.1,59 ; v1(27.1,58.8) 26.9,58.8 ; v1(27.1,58.8) 27.41,58.8 ; v1(27.1,58.8) 27.1,58.54 ; v1(33.07,78.25) 33.07,78.55 ; v1(33.07,78.25) 32.85,78.25 ; v1(33.07,78.25) 33.07,78.02 ; v1(33.07,78.25) 33.34,78.25 ; v1(11.3,27.2) 11.3,27.36 ; v1(11.3,27.2) 11.49,27.2 ; v1(11.3,27.2) 11.3,26.82 ; v1(11.3,27.2) 11.14,27.2 ; SHORT.1 10.54,74.79 10.91,74.42 v1(10.91,74.15) ; 40.8,60.25 v1(40.95,60.25) ; v1(40.95,60.25) 40.95,59.96 ; v1(40.95,60.25) 40.95,60.4 ; v1(40.95,60.25) 41.23,60.25 ; J8.6 26.9,22.65 v1(26.2,23.35) ; v1(27.75,34.4) 27.75,34.7 ; v1(27.75,34.4) 27.96,34.4 ; v1(27.75,34.4) 27.52,34.4 ; v1(27.75,34.4) 27.75,34.19 ; 35.39,19.7 v1(35.65,19.7) ; v1(35.65,19.7) 35.88,19.7 ; v1(35.65,19.7) 35.65,20.01 ; v1(35.65,19.7) 35.65,19.47 ; 15.05,66.75 v1(15.25,66.75) ; v1(15.25,66.75) 15.5,66.75 ; v1(15.25,66.75) 15.25,66.95 ; v1(15.25,66.75) 15.25,66.43 ; v1(14.67,82.42) 14.89,82.42 ; v1(14.67,82.42) 14.53,82.42 ; v1(14.67,82.42) 14.67,82.28 ; v1(14.67,82.42) 14.67,82.78 ; v1(27.7,30) 27.7,30.18 ; v1(27.7,30) 27.7,29.66 ; v1(27.7,30) 27.52,30 ; v1(27.7,30) 27.92,30 ; v1(31.4,80.55) 31.4,80.83 ; v1(31.4,80.55) 31.11,80.55 ; v1(31.4,80.55) 31.4,80.27 ; v1(31.4,80.55) 31.68,80.55 ; v1(16.5,26) 16.5,26.15 ; v1(16.5,26) 16.5,25.77 ; v1(16.5,26) 16.16,26 ; v1(16.5,26) 16.65,26 ; v1(18.1,24.35) 18.3,24.35 ; v1(18.1,24.35) 18.1,23.98 ; v1(18.1,24.35) 18.1,24.54 ; v1(18.1,24.35) 17.91,24.35 ; 31.7,16.65 v1(31.7,17) ; v1(31.7,17) 31.87,17 ; v1(31.7,17) 31.7,17.17 ; v1(31.7,17) 31.49,17 ; 13.9,76.35 v1(13.9,76.65) ; v1(13.9,76.65) 13.9,76.83 ; v1(13.9,76.65) 14.08,76.65 ; v1(13.9,76.65) 13.64,76.65 ; v1(24.55,8.75) 24.85,8.75 ; v1(24.55,8.75) 24.55,8.93 ; v1(24.55,8.75) 24.55,8.48 ; v1(24.55,8.75) 24.37,8.75 ; 17,17.22 v1(17,17.4) ; v1(17,17.4) 16.76,17.4 ; v1(17,17.4) 17,17.73 ; v1(17,17.4) 17.18,17.4 ; v1(33.25,25.4) 33.65,25.4 ; v1(33.25,25.4) 33.25,25.24 ; v1(33.25,25.4) 33.1,25.4 ; v1(33.25,25.4) 33.25,25.55 ; 13,63.59 v1(13,63.9) ; v1(13,63.9) 13.25,63.9 ; v1(13,63.9) 13,64.13 ; v1(13,63.9) 12.77,63.9 ; 11.04,25.95 v1(11.3,25.95) ; v1(11.3,25.95) 11.3,26.23 ; v1(11.3,25.95) 11.59,25.95 ; v1(11.3,25.95) 11.3,25.69 ; v1(34.6,49.7) 34.77,49.7 ; v1(34.6,49.7) 34.24,49.7 ; v1(34.6,49.7) 34.6,49.91 ; v1(34.6,49.7) 34.6,49.53 ; v1(29.35,48) 29.35,48.24 ; v1(29.35,48) 29.15,48 ; v1(29.35,48) 29.35,47.8 ; v1(29.35,48) 29.68,48 ; 38.05,67.95 v1(38.05,68.1) ; v1(38.05,68.1) 38.46,68.1 ; v1(38.05,68.1) 37.9,68.1 ; v1(38.05,68.1) 38.05,68.25 ; 30.66,81.22 v1(30.82,81.22) ; v1(30.82,81.22) 30.82,81.39 ; v1(30.82,81.22) 31,81.22 ; v1(30.82,81.22) 30.82,80.84 ; 20.9,52.29 v1(20.9,52.55) ; v1(20.9,52.55) 20.9,52.8 ; v1(20.9,52.55) 20.65,52.55 ; v1(20.9,52.55) 21.21,52.55 ; v1(35.4,76.5) 35.4,76.83 ; v1(35.4,76.5) 35.55,76.5 ; v1(35.4,76.5) 35.4,76.35 ; v1(35.4,76.5) 35.16,76.5 ; v1(29.14,59.61) 29.14,59.9 ; v1(29.14,59.61) 29.14,59.34 ; v1(29.14,59.61) 29.41,59.61 ; v1(29.14,59.61) 28.86,59.61 ; v1(19.6,18.35) 19.77,18.35 ; v1(19.6,18.35) 19.6,18.52 ; v1(19.6,18.35) 19.6,18.12 ; v1(19.6,18.35) 19.26,18.35 ; 16.4,29.08 v1(16.4,29.3) ; v1(16.4,29.3) 16.18,29.3 ; v1(16.4,29.3) 16.63,29.3 ; v1(16.4,29.3) 16.4,29.63 ; v1(33.65,22.95) 33.65,23.12 ; v1(33.65,22.95) 33.48,22.95 ; v1(33.65,22.95) 33.84,22.95 ; v1(33.65,22.95) 33.65,22.57 ; 23.4,50.93 v1(23.4,51.1) ; v1(23.4,51.1) 23.73,51.1 ; v1(23.4,51.1) 23.23,51.1 ; v1(23.4,51.1) 23.4,51.34 ; v1(13.35,22.85) 13.35,23.08 ; v1(13.35,22.85) 13.58,22.85 ; v1(13.35,22.85) 13.35,22.62 ; v1(13.35,22.85) 13.01,22.85 ; 21.5,26.25 v1(21.5,26.6) ; v1(21.5,26.6) 21.5,26.79 ; v1(21.5,26.6) 21.29,26.6 ; v1(21.5,26.6) 21.7,26.6 ; 11.1,28.15 v1(11.3,28.15) ; v1(11.3,28.15) 11.52,28.15 ; v1(11.3,28.15) 11.3,27.95 ; v1(11.3,28.15) 11.3,28.49 ; v1(27.75,31.7) 27.92,31.7 ; v1(27.75,31.7) 27.75,31.37 ; v1(27.75,31.7) 27.75,31.87 ; v1(27.75,31.7) 27.52,31.7 ; 28.92,48.8 v1(29.2,48.8) ; v1(29.2,48.8) 29.35,48.8 ; v1(29.2,48.8) 29.2,49.09 ; v1(29.2,48.8) 29.2,48.65 ; v1(10.75,71.2) 10.75,71.5 ; v1(10.75,71.2) 10.55,71.2 ; v1(10.75,71.2) 11.02,71.2 ; v1(10.75,71.2) 10.75,70.93 ; 21.85,15.85 v1(21.85,16.05) ; v1(21.85,16.05) 22.05,16.05 ; v1(21.85,16.05) 21.51,16.05 ; v1(21.85,16.05) 21.85,16.27 ; 11.25,24.04 v1(11.25,24.25) ; v1(11.25,24.25) 11.04,24.25 ; v1(11.25,24.25) 11.25,24.48 ; v1(11.25,24.25) 11.58,24.25 ; v1(10.8,67.2) 10.8,67.49 ; v1(10.8,67.2) 10.8,67.02 ; v1(10.8,67.2) 10.98,67.2 ; v1(10.8,67.2) 10.55,67.2 ; 10.26,45.4 v1(10.5,45.4) ; v1(10.5,45.4) 10.5,45.23 ; v1(10.5,45.4) 10.5,45.72 ; v1(10.5,45.4) 10.67,45.4 ; v1(40.4,21.2) 40.65,21.2 ; v1(40.4,21.2) 40.4,20.92 ; v1(40.4,21.2) 40.21,21.2 ; v1(40.4,21.2) 40.4,21.39 ; v1(20.25,7.3) 20.64,7.3 ; v1(20.25,7.3) 20.25,7.12 ; v1(20.25,7.3) 20.25,7.46 ; v1(20.25,7.3) 20.09,7.3 ; 12.52,47.25 v1(12.75,47.25) ; v1(12.75,47.25) 12.93,47.25 ; v1(12.75,47.25) 12.75,47.43 ; v1(12.75,47.25) 12.75,46.91 ; 15,77.45 v1(15.25,77.45) ; v1(15.25,77.45) 15.25,77.18 ; v1(15.25,77.45) 15.54,77.45 ; v1(15.25,77.45) 15.25,77.7 ; 37.32,79.99 v1(37.32,80.22) ; v1(37.32,80.22) 37.58,80.22 ; v1(37.32,80.22) 37.32,80.54 ; v1(37.32,80.22) 37.09,80.22 ; 28.8,49.49 v1(28.8,49.8) ; v1(28.8,49.8) 28.65,49.8 ; v1(28.8,49.8) 29.05,49.8 ; v1(28.8,49.8) 28.8,49.95 ; 35.95,19.2 v1(36.2,19.2) ; v1(36.2,19.2) 36.2,19.45 ; v1(36.2,19.2) 36.2,18.89 ; v1(36.2,19.2) 36.46,19.2 ; 24.35,18.35 v1(24.65,18.35) ; v1(24.65,18.35) 24.65,18.08 ; v1(24.65,18.35) 24.65,18.56 ; v1(24.65,18.35) 24.86,18.35 ; v1(22.95,16.65) 23.17,16.65 ; v1(22.95,16.65) 22.95,16.87 ; v1(22.95,16.65) 22.95,16.38 ; v1(22.95,16.65) 22.65,16.65 ; v1(19,11.45) 19.15,11.45 ; v1(19,11.45) 19,11.3 ; v1(19,11.45) 18.75,11.45 ; v1(19,11.45) 19,11.77 ; v1(19.2,52.55) 19.51,52.55 ; v1(19.2,52.55) 19.2,52.8 ; v1(19.2,52.55) 18.95,52.55 ; v1(19.2,52.55) 19.2,52.3 ; v1(16.4,33.75) 16.4,34.16 ; v1(16.4,33.75) 16.25,33.75 ; v1(16.4,33.75) 16.4,33.6 ; v1(16.4,33.75) 16.56,33.75 ; v1(11.3,29.35) 11.59,29.35 ; v1(11.3,29.35) 11.04,29.35 ; v1(11.3,29.35) 11.3,29.62 ; v1(11.3,29.35) 11.3,29.09 ; v1(8.2,41.4) 8.2,41.8 ; v1(8.2,41.4) 8.37,41.4 ; v1(8.2,41.4) 8.2,41.24 ; v1(8.2,41.4) 8.04,41.4 ; 8.72,47.5 v1(8.72,47.72) ; v1(8.72,47.72) 8.5,47.72 ; v1(8.72,47.72) 9.04,47.72 ; v1(8.72,47.72) 8.72,47.98 ; 18.35,16.94 v1(18.35,17.2) ; v1(18.35,17.2) 18.11,17.2 ; v1(18.35,17.2) 18.66,17.2 ; v1(18.35,17.2) 18.35,17.44 ; 28.02,13.5 v1(28.3,13.5) ; v1(28.3,13.5) 28.3,13.25 ; v1(28.3,13.5) 28.3,13.78 ; v1(28.3,13.5) 28.55,13.5 ; 22.09,51.1 v1(22.45,51.1) ; v1(22.45,51.1) 22.45,50.96 ; v1(22.45,51.1) 22.45,51.31 ; v1(22.45,51.1) 22.59,51.1 ; v1(14.8,53.65) 14.8,53.87 ; v1(14.8,53.65) 14.96,53.65 ; v1(14.8,53.65) 14.45,53.65 ; v1(14.8,53.65) 14.8,53.49 ; v1(13.35,58.05) 13.25,58.05 12.45,57.25 11.85,57.25 ; 13.86,20.3 v1(14.05,20.3) ; v1(14.05,20.3) 14.05,20.49 ; v1(14.05,20.3) 14.42,20.3 ; v1(14.05,20.3) 14.05,20.11 ; 25.28,14.75 v1(25.45,14.75) ; v1(25.45,14.75) 25.45,14.39 ; v1(25.45,14.75) 25.45,14.92 ; v1(25.45,14.75) 25.64,14.75 ; 11.41,74.79 v1(12.05,74.15)
  BOTTOM w0.5: J4.2 10.58,76.83 v1(11.13,77.38)
  vias: v1(4.85,52.7) v1(4.85,60.05) v1(4.85,54.9) v1(5,56.85) v1(4.95,53.95) v1(5.4,48.7) v1(5.56,56.18) v1(5.85,48.05) v1(6.02,45.35) v1(6,43.5) v1(6.05,42.45) v1(6.3,56.95) v1(6.4,44.46) v1(6.45,48.42) v1(6.77,42.65) v1(8.6,46.95) v1(9.1,63.75) v1(9.25,41.3) v1(9.75,63.85) v1(10.22,39.1) v1(10.47,64.3) v1(10.8,82.33) v1(10.84,73.41) v1(10.8,70.35) v1(10.9,68.8) v1(11.25,37) v1(11.25,35.2) v1(11.25,30.2) v1(11.3,22.3) v1(11.25,20.4) v1(11.3,13.95) v1(11.25,9.3) v1(11.25,7.6) v1(11.25,5.7) v1(11.35,16) v1(11.65,67.65) v1(11.7,8.45) v1(11.77,82.6) v1(12.17,77.45) v1(12.2,56.9) v1(12.35,15.55) v1(12.5,56.4) v1(12.65,41.15) v1(12.85,82.77) v1(12.75,14.6) v1(13.22,77.8) v1(13.2,5) v1(13.45,44.35) v1(13.5,43.6) v1(13.7,38.8) v1(13.9,78.75) v1(14.02,80.58) v1(14.07,81.65) v1(14.1,75) v1(14.2,26.8) v1(14.4,54.1) v1(14.8,78.65) v1(14.75,43.8) v1(14.85,13.9) v1(15.15,76.5) v1(15.3,65.7) v1(15.3,64.2) v1(15.29,62.89) v1(15.3,13.25) v1(15.42,55.12) v1(15.4,53.65) v1(15.75,7.98) v1(16.25,17.6) v1(16.3,82.7) v1(16.4,31.35) v1(16.35,27.35) v1(16.45,18.3) v1(16.8,77.5) v1(16.9,40.92) v1(16.9,10.45) v1(17.8,8.5) v1(17.85,6.7) v1(18,15.3) v1(18.05,34.05) v1(18.05,31.95) v1(18.1,30.3) v1(18.1,27.45) v1(18.1,14.4) v1(18.9,26.6) v1(18.9,14.15) v1(19.9,17.55) v1(20.4,51.1) v1(20.45,26.6) v1(20.6,10.05) v1(20.7,23.85) v1(20.72,14.65) v1(21.35,51.1) v1(21.45,17.15) v1(21.9,5.2) v1(22.15,18.35) v1(22.45,26.6) v1(22.95,18.2) v1(24.75,4.6) v1(25.6,17.25) v1(26.1,18.35) v1(26.45,9.85) v1(27,7.9) v1(27.05,18.25) v1(27.15,11.45) v1(27.45,14.2) v1(27.7,32.45) v1(27.7,29.15) v1(28,50.9) v1(28.3,49.4) v1(28.25,4.85) v1(28.4,17.4) v1(28.55,34.4) v1(28.7,78.1) v1(28.65,11.6) v1(29,40) v1(29.1,16.75) v1(29.3,82.75) v1(29.35,47.15) v1(29.5,14.5) v1(29.5,12.75) v1(30.05,47.2) v1(30.1,16.75) v1(30.8,32.2) v1(30.97,82.05) v1(31.47,79.75) v1(31.65,5.45) v1(31.95,82.02) v1(32.35,75.8) v1(32.35,16.85) v1(32.45,17.55) v1(32.85,82.8) v1(32.85,20.2) v1(33.05,23.6) v1(33.3,24.45) v1(33.35,32.4) v1(33.35,19.4) v1(33.45,31.4) v1(33.7,82.67) v1(33.7,61.65) v1(33.8,65.05) v1(33.8,25.1) v1(34.1,13.55) v1(34.37,73.62) v1(34.45,72.15) v1(34.5,54.55) v1(34.5,52.9) v1(34.55,44.35) v1(34.55,40.5) v1(34.55,38.7) v1(34.55,18.4) v1(34.45,12.2) v1(34.45,6.5) v1(34.55,46.05) v1(34.6,43.3) v1(34.6,37.75) v1(34.6,34.8) v1(34.6,31.7) v1(34.6,30.8) v1(34.55,17.25) v1(35.3,19.1) v1(35.5,28.85) v1(35.87,77.85) v1(36.02,56.67) v1(36.05,28.35) v1(37.05,79) v1(37.65,81.4) v1(37.75,23.3) v1(38.05,79.02) v1(37.95,59.2) v1(38.55,74.45) v1(38.6,61.35) v1(39.5,63.05) v1(39.55,26.7) v1(39.6,22.3) v1(39.55,21.7) v1(39.6,19.45) v1(39.8,28.1) v1(40.3,27.5) v1(40.35,20.2) v1(40.35,19.15) v1(40.45,57.5) v1(40.87,79) v1(40.9,63.05) v1(41,75.2) v1(41.5,80.3) v1(41.7,65.15) v1(41.75,70.35) v1(41.75,68.05) v1(41.9,75.55)
